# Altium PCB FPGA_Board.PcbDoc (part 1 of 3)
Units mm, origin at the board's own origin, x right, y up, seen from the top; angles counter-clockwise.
Board outline 130 x 90 mm, 4 copper layers (Component Side, Signal Layer 1, Signal Layer 2, Bottom Layer), stack 0.651 mm thick; 303 components, 175 nets, 968 pads, 775 vias.
Unrouted connection lines stored in the file: 193.
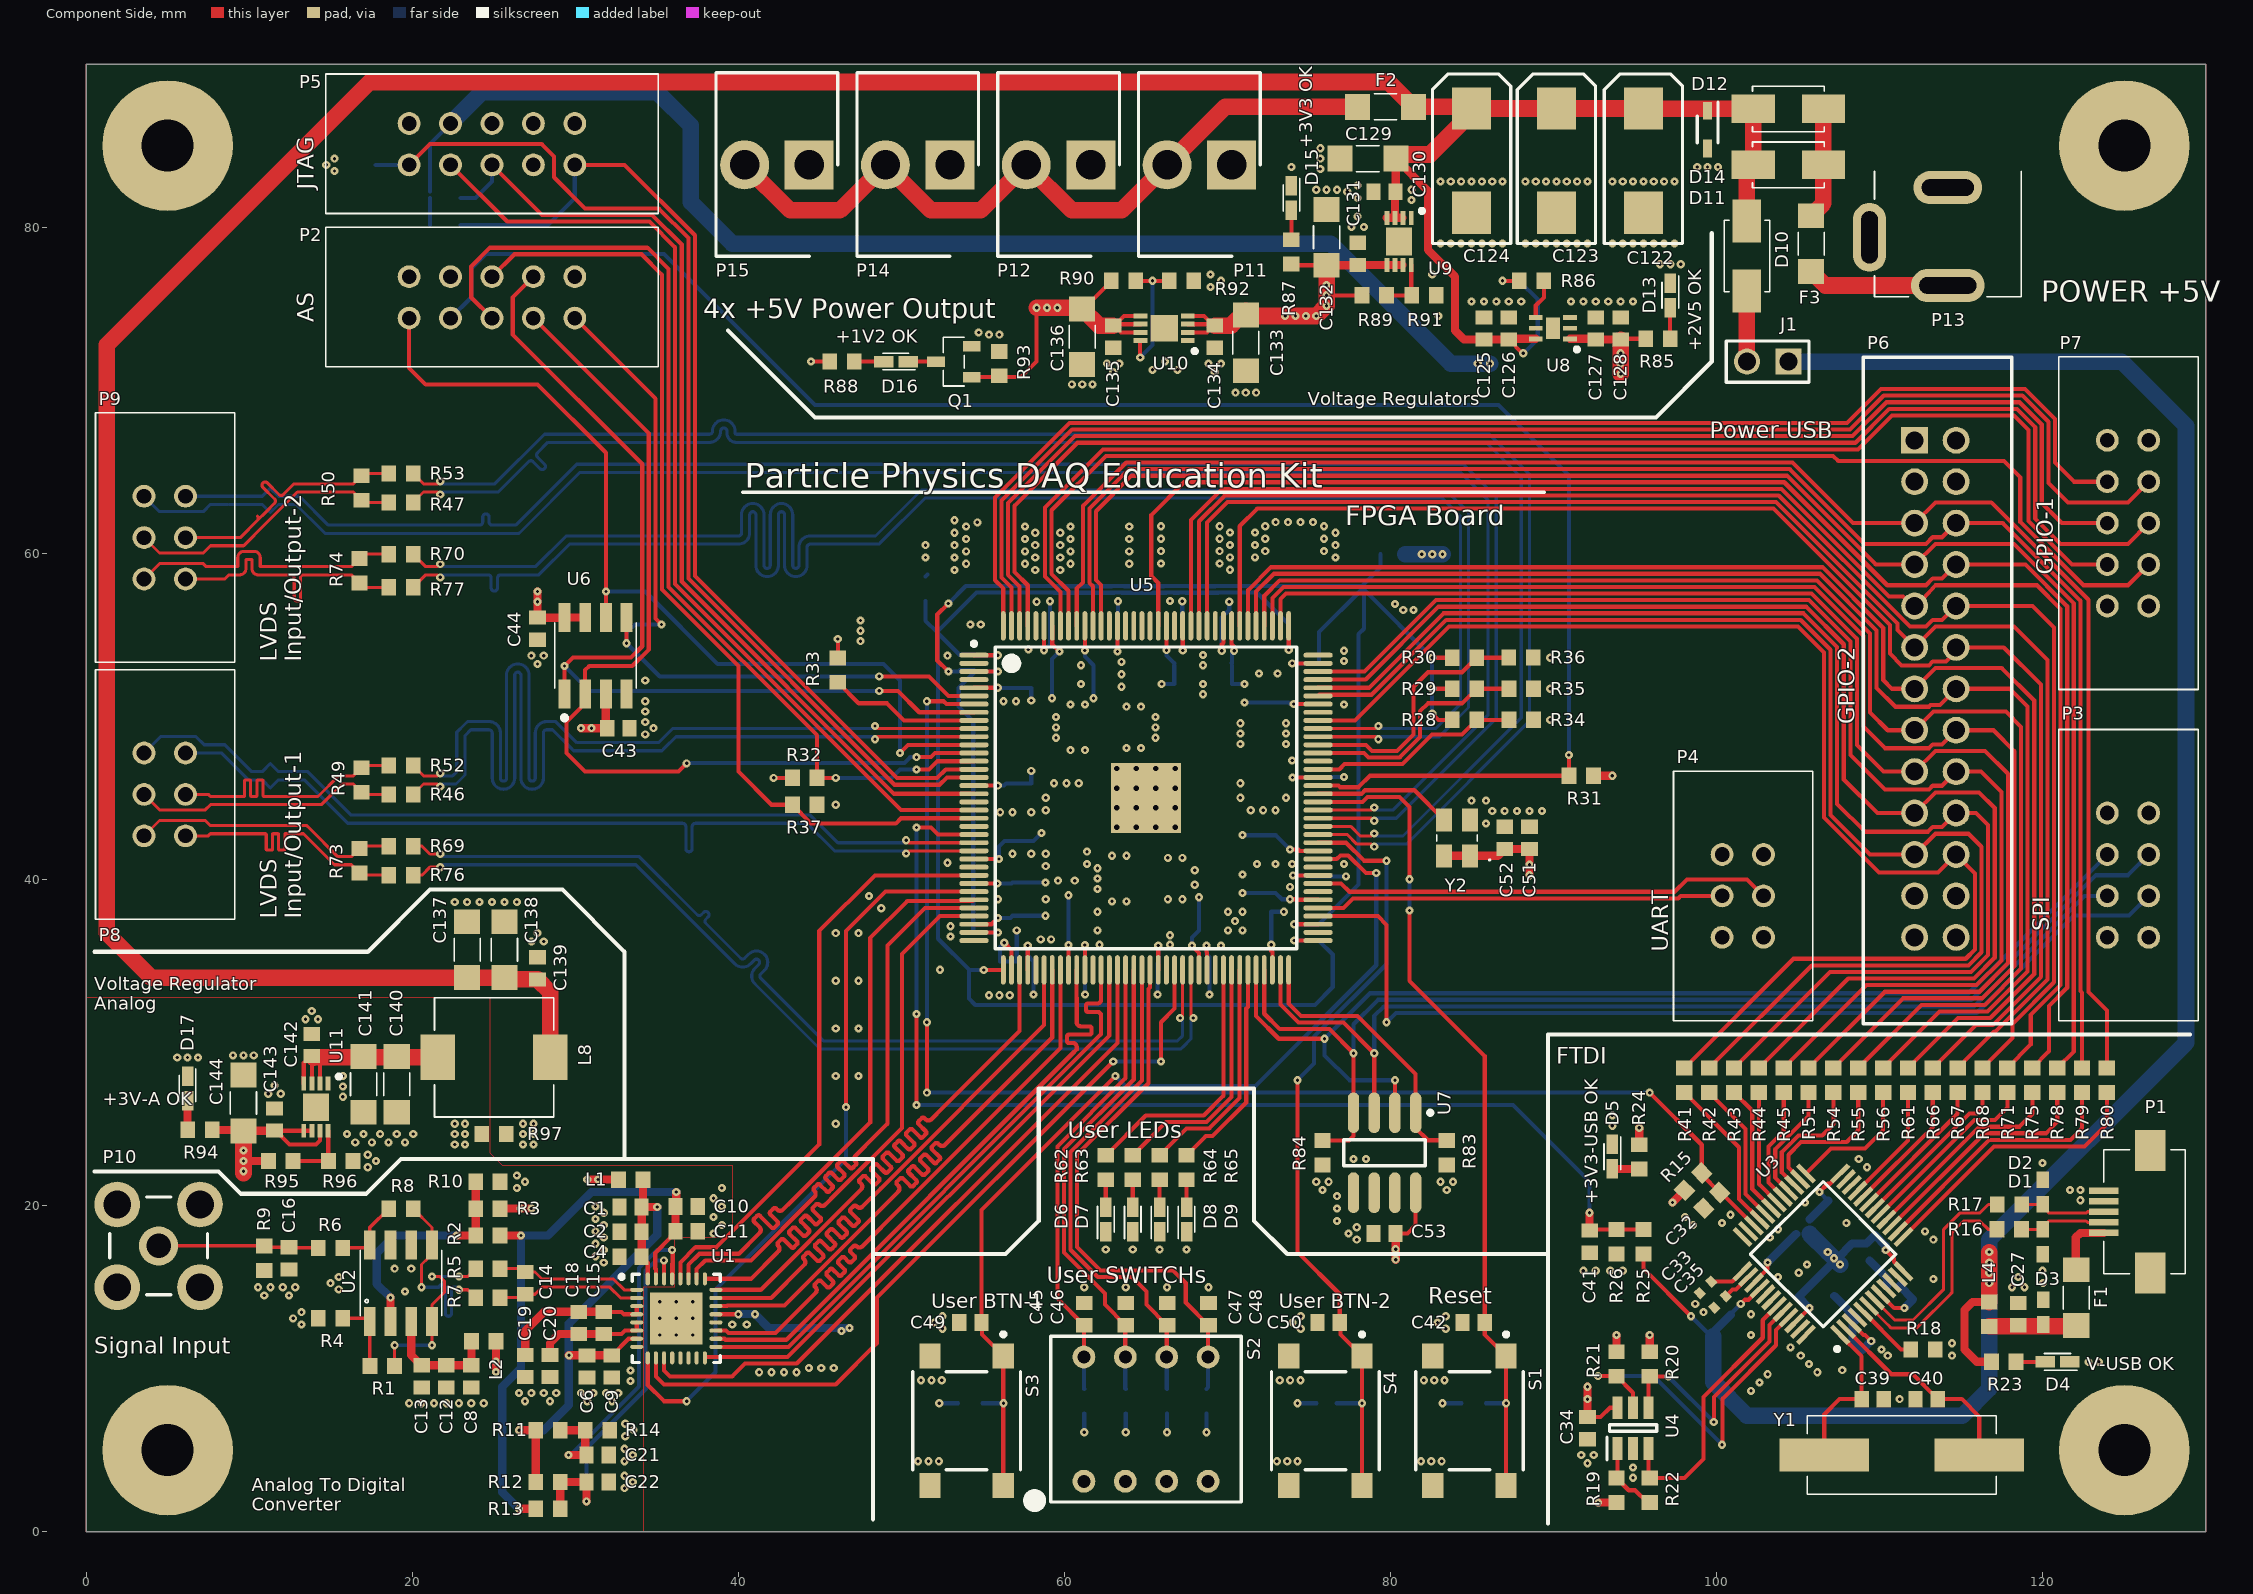
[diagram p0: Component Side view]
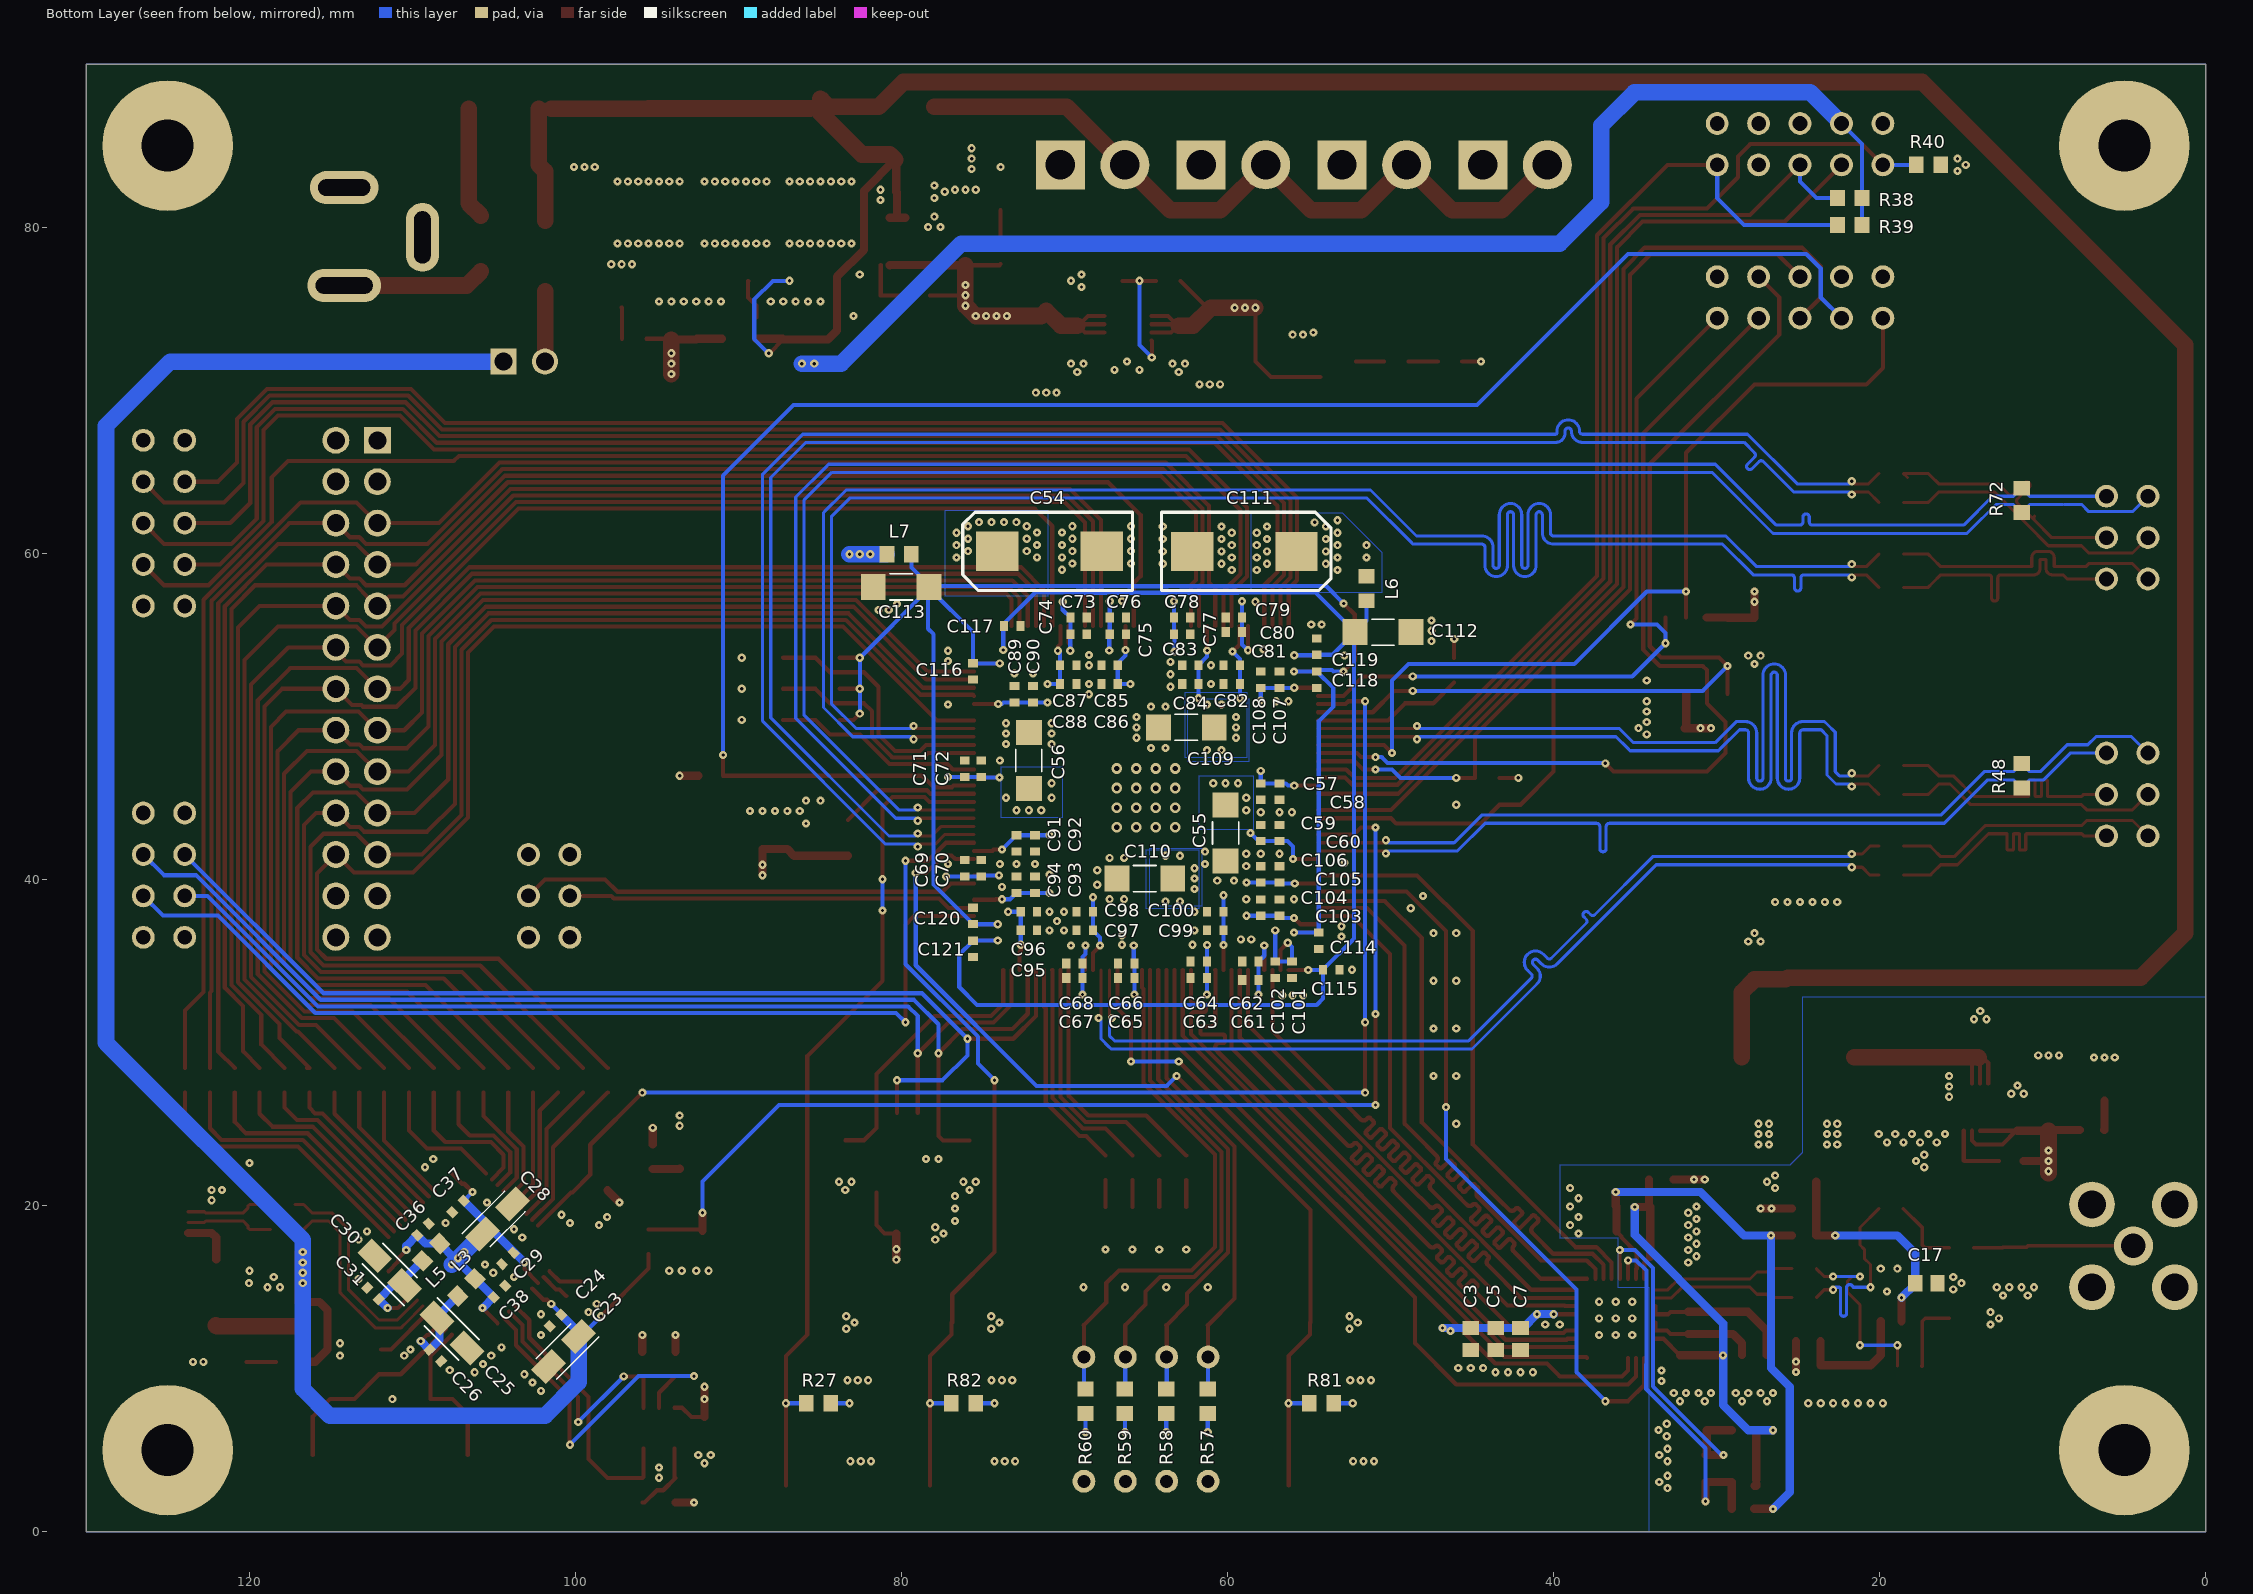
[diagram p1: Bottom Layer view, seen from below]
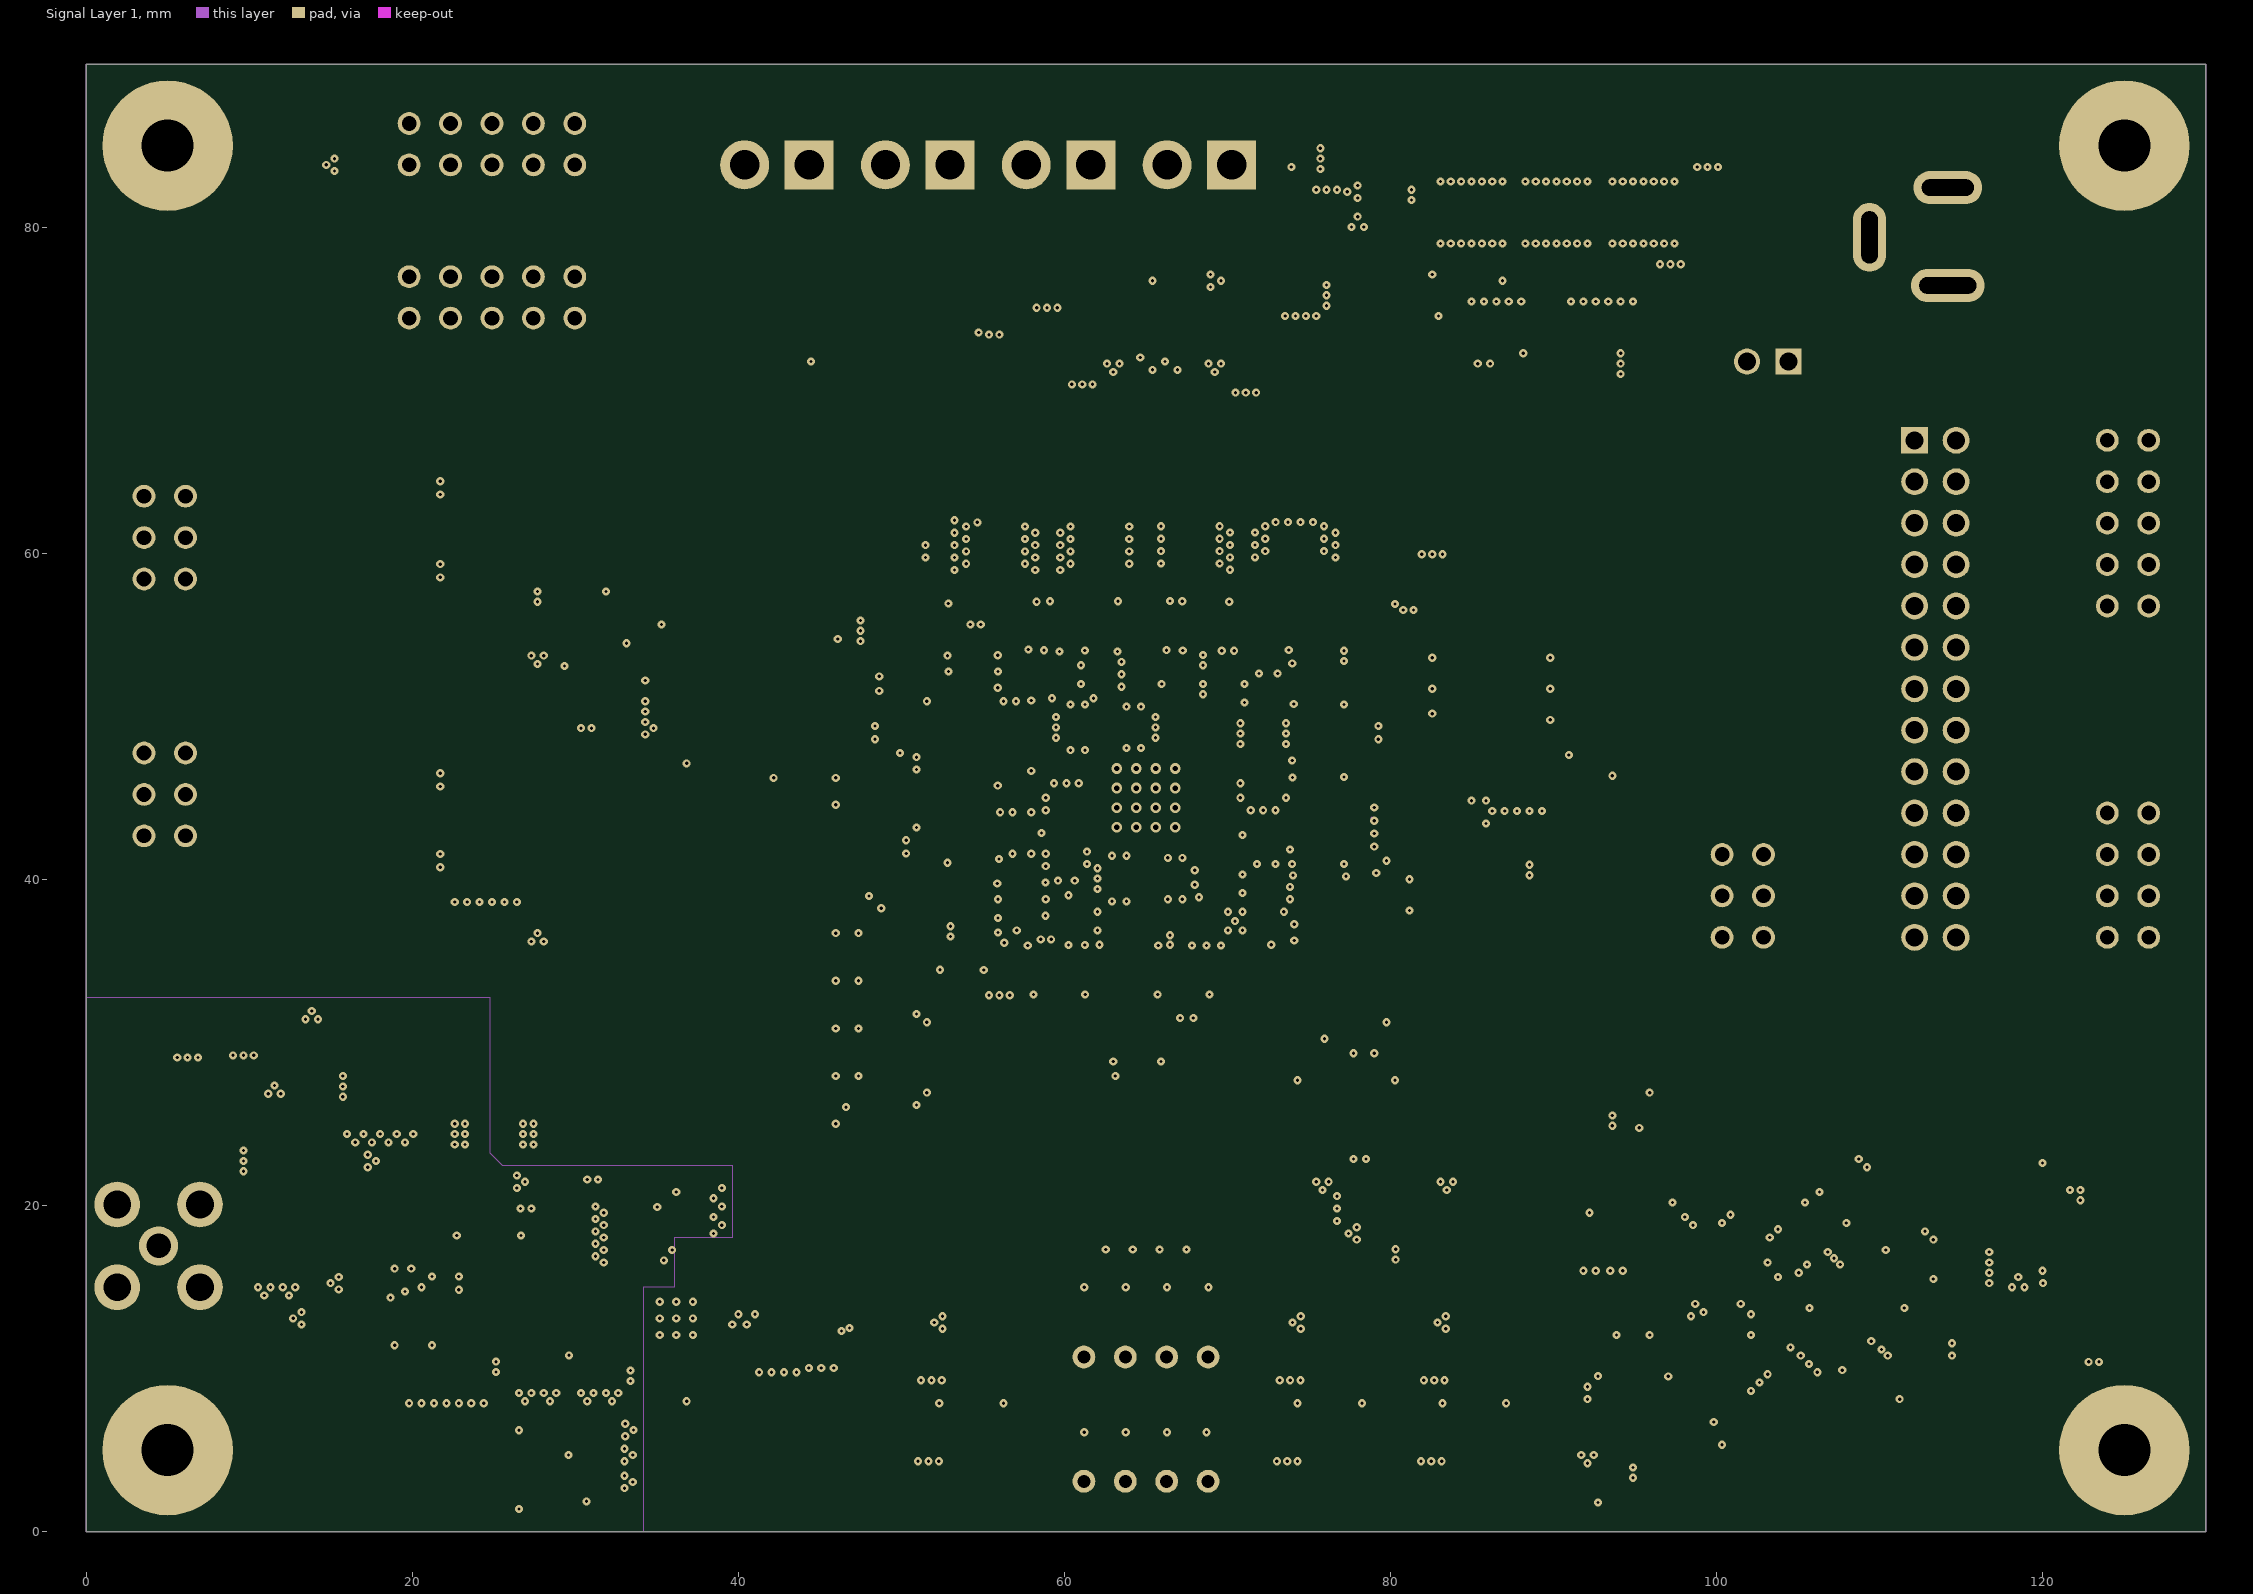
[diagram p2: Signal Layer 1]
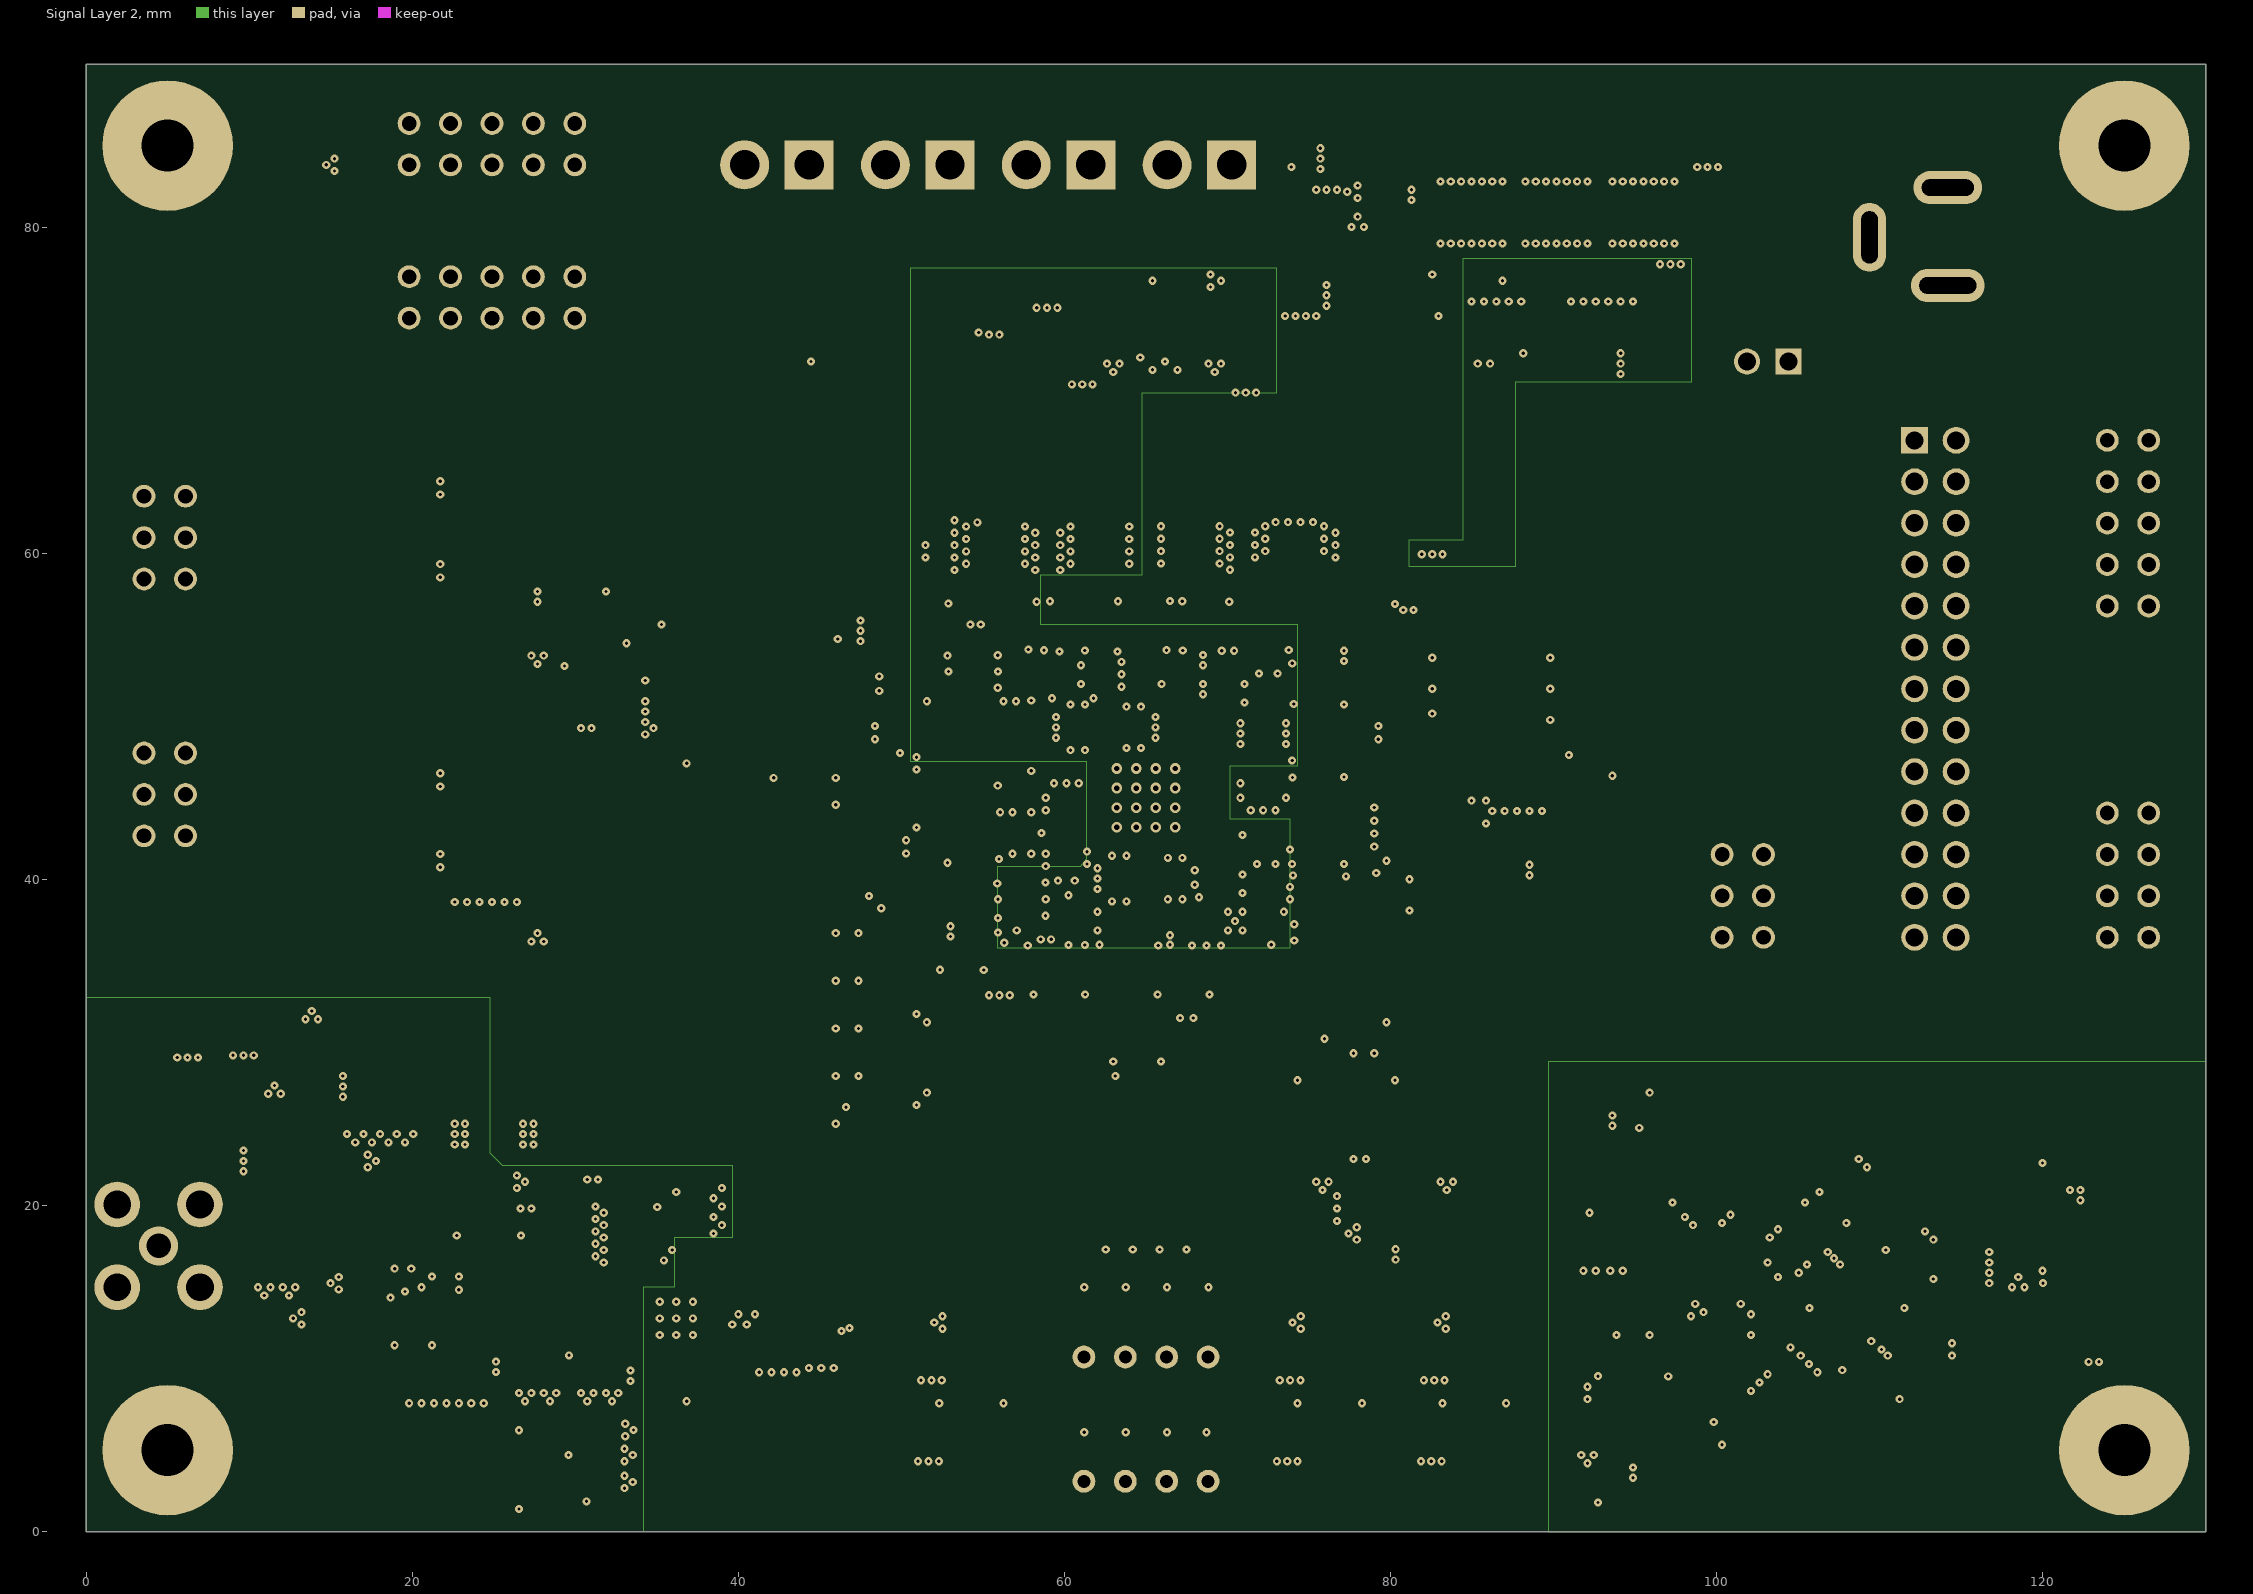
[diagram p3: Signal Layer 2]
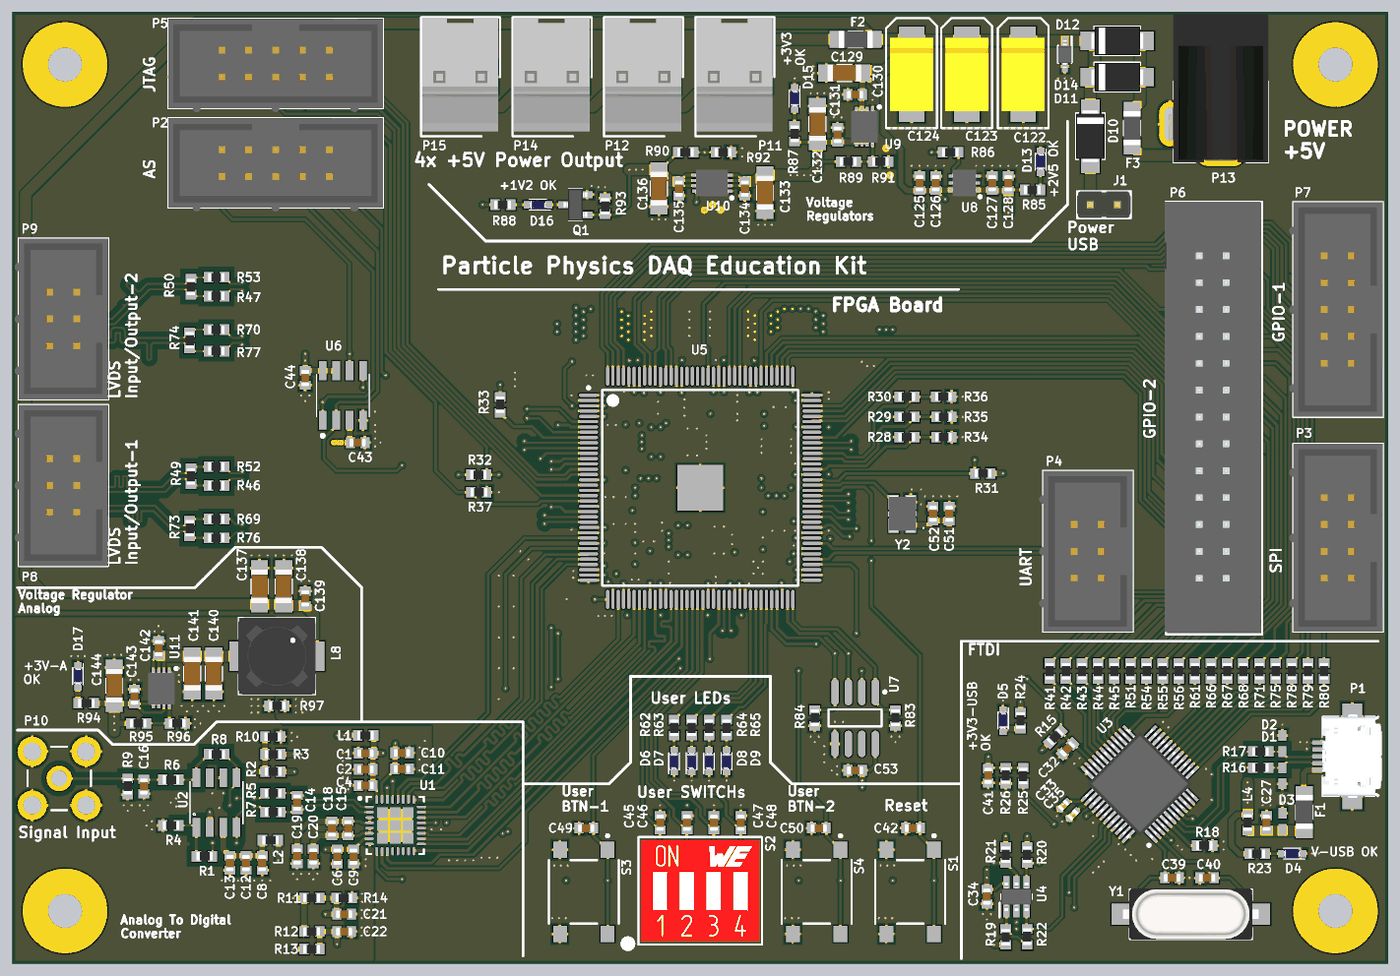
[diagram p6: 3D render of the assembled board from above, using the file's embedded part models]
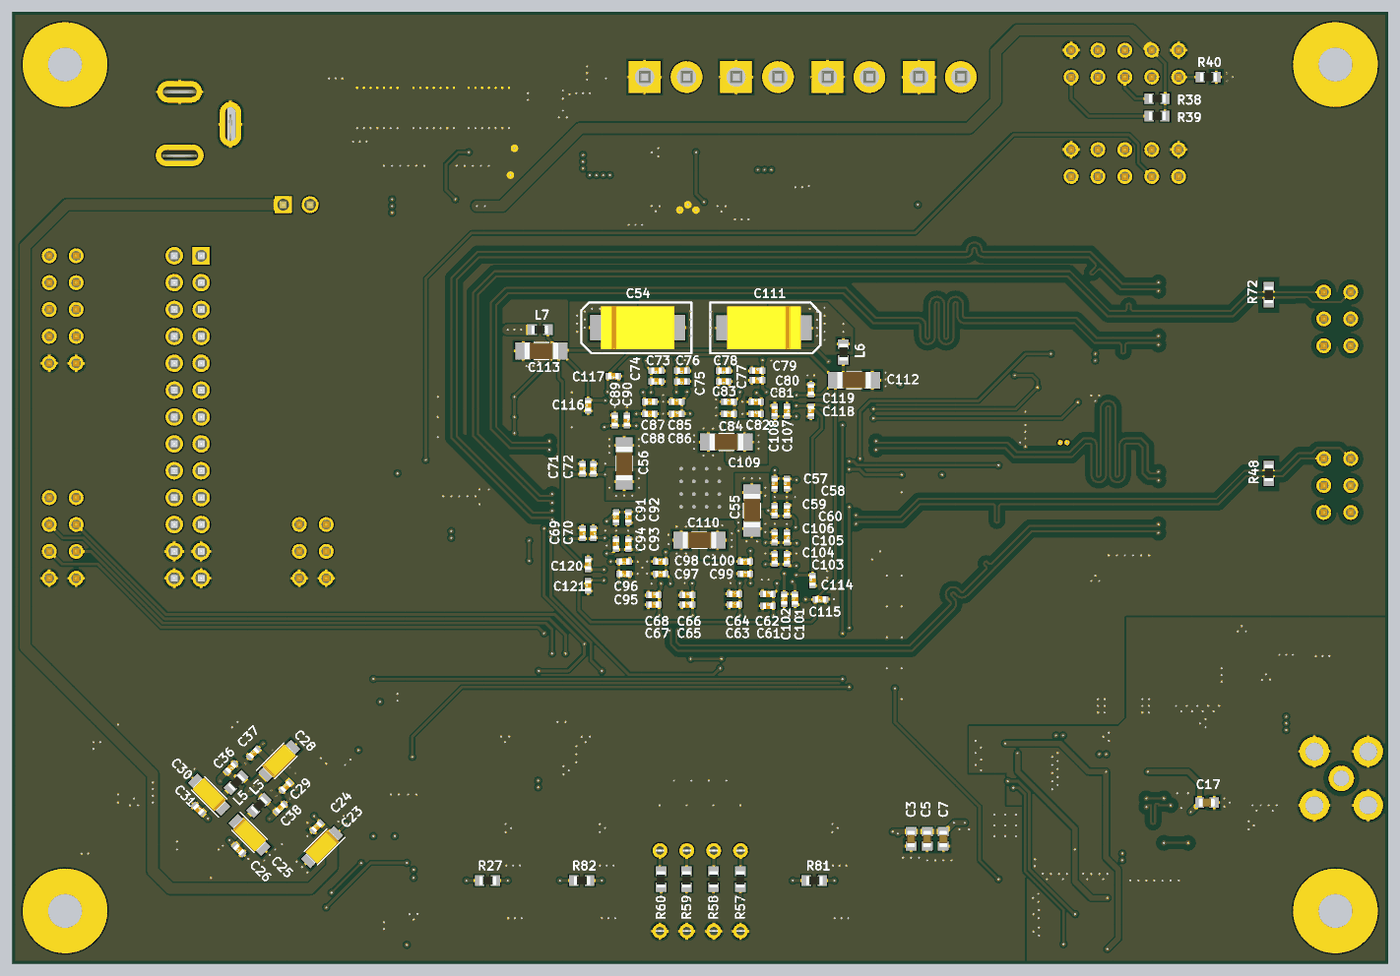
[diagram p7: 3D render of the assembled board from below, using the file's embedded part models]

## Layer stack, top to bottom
Top Solder: solder mask 0.0102, Solder Resist, Dk 3.5
Component Side: signal copper 0.0356
Dielectric 1: prepreg 0.127, FR-4, Dk 4.2
Signal Layer 1: signal copper 0.036
Dielectric 3: core 0.254, Dk 4.2
Signal Layer 2: signal copper 0.036
Dielectric 2: prepreg 0.127, Dk 4.2
Bottom Layer: signal copper 0.0356
Solder Side: solder mask 0.0102, Solder Resist, Dk 3.5

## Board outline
0,0 130,0 130,90 0,90

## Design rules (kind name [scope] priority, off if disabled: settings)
AcuteAngle [All] p1: minimum=6.00000000000000E+0001 checktracksonly=FALSE
BoardOutlineClearance [All] p1: gap=0.3 ignorepadtopadclearanceinfootprint=FALSE
Clearance Clearance_50R [InNetClass('50R')] p1: gap=0.15 ignorepadtopadclearanceinfootprint=FALSE except(0: Arc-Hole Track-Hole SMDPad-Hole THPad-Hole Via-Hole Fill-Hole Poly-Hole Region-Hole Text-Hole; 0.5: Arc-Fill Arc-Poly Arc-Region Track-Fill Track-Poly Track-Region SMDPad-Fill SMDPad-Poly SMDPad-Region THPad-Fill THPad-Poly THPad-Region Via-Fill Via-Poly Via-Region Fill-Fill Fill-Poly Fill-Region Poly-Poly Poly-Region Region-Region)
Clearance Clearance_DiffPair [(InDifferentialPairClass('All Differential Pairs'))] p2: gap=0.15 ignorepadtopadclearanceinfootprint=FALSE except(0: Arc-Hole Track-Hole SMDPad-Hole THPad-Hole Via-Hole Fill-Hole Poly-Hole Region-Hole Text-Hole; 0.5: Arc-Poly Track-Poly SMDPad-Poly THPad-Poly Via-Poly Fill-Poly Poly-Poly)
Clearance [All] p3: gap=0.15 ignorepadtopadclearanceinfootprint=FALSE except(0: Arc-Hole Track-Hole SMDPad-Hole THPad-Hole Via-Hole Fill-Hole Poly-Hole Region-Hole Text-Hole)
DiffPairsRouting [All] p1: maxlimit=0.31 minlimit=0.31 mostfreqgap=0.31 toplayer_minwidth=0.19 toplayer_maxwidth=0.19 toplayer_prefwidth=0.19 midlayer1_minwidth=0.19 midlayer1_maxwidth=0.19 midlayer1_prefwidth=0.19 midlayer2_minwidth=0.19 midlayer2_maxwidth=0.19 midlayer2_prefwidth=0.19 bottomlayer_minwidth=0.19 bottomlayer_maxwidth=0.19 bottomlayer_prefwidth=0.19 maxuncoupledlength=12.7
HoleSize [All] p1: absolutevalues=TRUE maxlimit=4 minlimit=0.025 maxpercent=80.000 minpercent=20.000
MatchedLengths MatchedLengths_1 [InNetClass('ADC_DATA')] p1: tolerance=1 checknetsindiffpair=FALSE checkdiffpairvsdiffpair=TRUE checkxsignals=TRUE checkothers=TRUE
MatchedLengths [All] p2: tolerance=1 checknetsindiffpair=TRUE checkdiffpairvsdiffpair=FALSE checkxsignals=FALSE checkothers=FALSE
MinimumSolderMaskSliver [All] p1: minsoldermaskwidth=0.065
PolygonConnect [All] p1: thpad.connectstyle=Relief thpad.reliefconductorwidth=0.254 thpad.reliefentries=4 thpad.polygonreliefangle="90 Angle" thpad.airgapwidth=0.254 smdpad.connectstyle=Relief smdpad.reliefconductorwidth=0.254 smdpad.reliefentries=4 smdpad.polygonreliefangle="90 Angle" smdpad.airgapwidth=0.254 via.connectstyle=Direct via.reliefconductorwidth=0.254 via.reliefentries=4 via.polygonreliefangle="90 Angle" via.airgapwidth=0.254
RoutingVias [All] p1: holewidth=0.2 width=0.5 viastyle="Through Hole" minholewidth=0.2 minwidth=0.5 maxholewidth=0.2 maxwidth=0.5
SilkToSilkClearance [All] p1: silktosilkclearance=0.1
SilkToSolderMaskClearance [IsPad] p1: minsilkscreentomaskgap=0.1 clearancetoexposedcopper=TRUE
SolderMaskExpansion [All] p1: expansion=0.102
Width Width_50R [InNetClass('50R')] p1: maxlimit=0.22 minlimit=0.22 preferedwidth=0.22
Width [All] p2: maxlimit=1.016 minlimit=0.254 preferedwidth=0.508
25 further rules are at their usual default settings.

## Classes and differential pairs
component class Main: P10
component class U_ADC: C1 C2 C3 C4 C5 C6 C7 C8 C9 C10 C11 C12 C13 C14 C15 C16 C17 C18 C19 C20 C21 C22 L1 L2 R1 R2 R3 R4 R5 R6 R7 R8 R9 R10 R11 R12 R13 R14 U1 U2
component class U_Communication: C23 C24 C25 C26 C27 C28 C29 C30 C31 C32 C33 C34 C35 C36 C37 C38 C39 C40 C41 D1 D2 D3 D4 D5 F1 L3 L4 L5 P1 R15 R16 R17 R18 R19 R20 R21 R22 R23 R24 R25 R26 U3 U4 Y1
component class U_FPGA_Power: C54 C55 C56 C57 C58 C59 C60 C61 C62 C63 C64 C65 C66 C67 C68 C69 C70 C71 C72 C73 C74 C75 C76 C77 C78 C79 C80 C81 C82 C83 C84 C85 C86 C87 C88 C89 C90 C91 C92 C93 C94 C95 C96 C97 C98 C99 C100 C101 C102 C103 C104 C105 C106 C107 C108 C109 C110 C111 C112 C113 C114 C115 C116 C117 C118 C119 C120 C121 L6 L7
component class U_FPGA: C42 C43 C44 C45 C46 C47 C48 C49 C50 C51 C52 C53 D6 D7 D8 D9 P2 P3 P4 P5 P6 P7 P8 P9 R27 R28 R29 R30 R31 R32 R33 R34 R35 R36 R37 R38 R39 R40 R41 R42 R43 R44 R45 R46 R47 R48 R49 R50 R51 R52 R53 R54 R55 R56 R57 R58 R59 R60 R61 R62 R63 R64 R65 R66 R67 R68 R69 R70 R71 R72 R73 R74 R75 R76 R77 R78 R79 R80 R81 R82 R83 R84 S1 S2 S3 S4 U5 U6 U7 Y2
component class U_Power: C122 C123 C124 C125 C126 C127 C128 C129 C130 C131 C132 C133 C134 C135 C136 C137 C138 C139 C140 C141 C142 C143 C144 D10 D11 D12 D13 D14 D15 D16 D17 F2 F3 J1 L8 P11 P12 P13 P14 P15 Q1 R85 R86 R87 R88 R89 R90 R91 R92 R93 R94 R95 R96 R97 U8 U9 U10 U11
net class 50R: NetC16_2 NetR1_1 NetR6_2
net class ADC_DATA: NetU1_16 NetU1_17 NetU1_18 NetU1_19 NetU1_22 NetU1_23 NetU1_24 NetU1_25 NetU1_26 NetU1_27
differential pair EXT_In: +EXT_In_P -EXT_In_N
differential pair EXT_Out0_R: +EXT_Out0_R_P -EXT_Out0_R_N
differential pair EXT_Out0: +EXT_Out0_P -EXT_Out0_N
differential pair EXT_Out1_R: +EXT_Out1_R_P -EXT_Out1_R_N
differential pair EXT_Out1: +EXT_Out1_P -EXT_Out1_N
differential pair Full_R: +Full_R_P -Full_R_N
differential pair Full: +Full_P -Full_N
differential pair InR: +InR_P -InR_N
differential pair In: +In_P -In_N
differential pair Ready_R: +Ready_R_P -Ready_R_N
differential pair Ready: +Ready_P -Ready_N
differential pair TRG: +TRG_P -TRG_N
differential pair D: +D_P -D_N
differential pair USB: +USB_P -USB_N

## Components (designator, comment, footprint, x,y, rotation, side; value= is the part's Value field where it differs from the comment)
C1 "1u" SMD_CAPACITOR_0603 33.389,19.911 r180 top
C2 "100nF" SMD_CAPACITOR_0603 33.389,18.387 r180 top
C3 "1uF" SMD_CAPACITOR_0603 45.085,11.811 r270 bottom
C4 "10nF" SMD_CAPACITOR_0603 33.389,16.863 r180 top
C5 "100nF" SMD_CAPACITOR_0603 43.561,11.811 r270 bottom
C6 "100nF" SMD_CAPACITOR_0603 30.722,10.132 r270 top
C7 "10nF" SMD_CAPACITOR_0603 42.037,11.811 r270 bottom
C8 "1u" SMD_CAPACITOR_0603 23.622,9.525 r270 top
C9 "10nF" SMD_CAPACITOR_0603 32.246,10.132 r270 top
C10 "2u2" SMD_CAPACITOR_0603 36.83,19.939 r180 top
C11 "100n" SMD_CAPACITOR_0603 36.83,18.415 r180 top
C12 "100nF" SMD_CAPACITOR_0603 22.098,9.525 r270 top
C13 "10nF" SMD_CAPACITOR_0603 20.574,9.525 r270 top
C14 "12p" SMD_CAPACITOR_0603 26.924,15.24 r90 top
C15 "100n" SMD_CAPACITOR_0603 31.738,12.799 r90 top
C16 "D.N.P." SMD_CAPACITOR_0603 12.446,16.764 r90 top
C17 "100nF" SMD_CAPACITOR_0603 17.145,15.24 r0 bottom
C18 "2u2" SMD_CAPACITOR_0603 30.214,12.799 r90 top
C19 "1u" SMD_CAPACITOR_0603 26.924,10.16 r90 top
C20 "1u" SMD_CAPACITOR_0603 28.448,10.16 r90 top
C21 "100nF" SMD_CAPACITOR_0603 31.369,4.699 r0 top
C22 "100nF" SMD_CAPACITOR_0603 31.369,3.048 r0 top
C23 "4u7" SMD_CAPACITOR_POL_A_3216 100.711,11.049 r315 bottom
C24 "100n" SMD_CAPACITOR_0402 101.219,12.954 r135 bottom
C25 "4u7" SMD_CAPACITOR_POL_A_3216 107.569,12.192 r225 bottom
C26 "100n" SMD_CAPACITOR_0402 108.585,10.795 r45 bottom
C27 "10n" SMD_CAPACITOR_0603 118.491,13.335 r270 top
C28 "4u7" SMD_CAPACITOR_POL_A_3216 104.775,19.177 r135 bottom
C29 "100n" SMD_CAPACITOR_0402 104.14,16.764 r135 bottom
C30 "4u7" SMD_CAPACITOR_POL_A_3216 111.379,16.002 r45 bottom
C31 "100n" SMD_CAPACITOR_0402 112.395,14.605 r225 bottom
C32 "10n" SMD_CAPACITOR_0603 99.695,20.32 r45 top
C33 "100n" SMD_CAPACITOR_0402 99.314,14.986 r45 top
C34 "100n" SMD_CAPACITOR_0603 92.075,6.35 r90 top
C35 "100n" SMD_CAPACITOR_0402 100.203,14.097 r45 top
C36 "100n" SMD_CAPACITOR_0402 109.347,18.542 r315 bottom
C37 "100n" SMD_CAPACITOR_0402 107.188,19.939 r135 bottom
C38 "100n" SMD_CAPACITOR_0402 104.648,14.732 r315 bottom
C39 "22p" SMD_CAPACITOR_0603 109.568,8.128 r180 top
C40 "22p" SMD_CAPACITOR_0603 112.87,8.128 r0 top
C41 "100n" SMD_CAPACITOR_0603 92.202,17.78 r90 top
C42 "10n" SMD_CAPACITOR_0603 85.09,12.827 r180 top
C43 "100n" SMD_CAPACITOR_0603 32.639,49.276 r180 top
C44 "100n" SMD_CAPACITOR_0603 27.686,55.372 r90 top
C45 "10n" SMD_CAPACITOR_0603 61.214,13.335 r270 top
C46 "10n" SMD_CAPACITOR_0603 63.754,13.335 r270 top
C47 "10n" SMD_CAPACITOR_0603 66.294,13.335 r270 top
C48 "10n" SMD_CAPACITOR_0603 68.834,13.335 r270 top
C49 "10n" SMD_CAPACITOR_0603 54.229,12.827 r180 top
C50 "10n" SMD_CAPACITOR_0603 76.2,12.827 r180 top
C51 "1u" SMD_CAPACITOR_0603 88.519,42.545 r90 top
C52 "100nF" SMD_CAPACITOR_0603 86.995,42.545 r90 top
C53 "100n" SMD_CAPACITOR_0603 79.629,18.288 r0 top
C54 "100u" CAP_Tantalum_D 70.913,60.118 r180 bottom
C55 "10u" SMD_CAPACITOR_1206 60.118,42.846 r90 bottom
C56 "10u" SMD_CAPACITOR_1206 72.183,47.291 r270 bottom
C57 "100n" SMD_CAPACITOR_0402 57.959,45.386 r90 bottom
C58 "10n" SMD_CAPACITOR_0402 56.816,45.386 r90 bottom
C59 "100n" SMD_CAPACITOR_0402 57.959,42.846 r270 bottom
C60 "10n" SMD_CAPACITOR_0402 56.816,42.846 r270 bottom
C61 "100n" SMD_CAPACITOR_0402 58.594,33.829 r180 bottom
C62 "10n" SMD_CAPACITOR_0402 58.594,34.972 r180 bottom
C63 "100n" SMD_CAPACITOR_0402 61.769,33.956 r180 bottom
C64 "10n" SMD_CAPACITOR_0402 61.769,34.972 r180 bottom
C65 "100n" SMD_CAPACITOR_0402 66.214,33.956 r180 bottom
C66 "10n" SMD_CAPACITOR_0402 66.214,34.845 r180 bottom
C67 "100n" SMD_CAPACITOR_0402 69.389,33.956 r180 bottom
C68 "10n" SMD_CAPACITOR_0402 69.389,34.845 r180 bottom
C69 "100n" SMD_CAPACITOR_0402 76.12,40.687 r270 bottom
C70 "10n" SMD_CAPACITOR_0402 75.104,40.687 r270 bottom
C71 "100n" SMD_CAPACITOR_0402 76.12,46.783 r270 bottom
C72 "10n" SMD_CAPACITOR_0402 75.104,46.783 r270 bottom
C73 "100n" SMD_CAPACITOR_0402 69.135,56.054 r0 bottom
C74 "10n" SMD_CAPACITOR_0402 69.135,55.038 r0 bottom
C75 "100n" SMD_CAPACITOR_0402 66.722,55.038 r0 bottom
C76 "10n" SMD_CAPACITOR_0402 66.722,56.054 r0 bottom
C77 "100n" SMD_CAPACITOR_0402 62.785,55.038 r0 bottom
C78 "10n" SMD_CAPACITOR_0402 62.785,56.054 r0 bottom
C79 "100n" SMD_CAPACITOR_0402 59.61,56.054 r180 bottom
C80 "10n" SMD_CAPACITOR_0402 59.61,55.165 r180 bottom
C81 "10n" SMD_CAPACITOR_0402 59.737,53.133 r180 bottom
C82 "100n" SMD_CAPACITOR_0402 59.737,51.99 r180 bottom
C83 "10n" SMD_CAPACITOR_0402 62.277,53.133 r180 bottom
C84 "100n" SMD_CAPACITOR_0402 62.277,51.99 r180 bottom
C85 "10n" SMD_CAPACITOR_0402 67.23,53.133 r180 bottom
C86 "100n" SMD_CAPACITOR_0402 67.23,51.99 r180 bottom
C87 "10n" SMD_CAPACITOR_0402 69.77,53.133 r0 bottom
C88 "100n" SMD_CAPACITOR_0402 69.77,51.99 r0 bottom
C89 "10n" SMD_CAPACITOR_0402 73.072,51.355 r270 bottom
C90 "100n" SMD_CAPACITOR_0402 71.929,51.355 r270 bottom
C91 "10n" SMD_CAPACITOR_0402 72.945,42.211 r90 bottom
C92 "100n" SMD_CAPACITOR_0402 71.802,42.211 r90 bottom
C93 "10n" SMD_CAPACITOR_0402 71.802,39.671 r270 bottom
C94 "100n" SMD_CAPACITOR_0402 72.945,39.671 r270 bottom
C95 "10n" SMD_CAPACITOR_0402 72.183,36.877 r0 bottom
C96 "100n" SMD_CAPACITOR_0402 72.183,38.02 r0 bottom
C97 "10n" SMD_CAPACITOR_0402 68.754,36.877 r180 bottom
C98 "100n" SMD_CAPACITOR_0402 68.754,38.02 r180 bottom
C99 "10n" SMD_CAPACITOR_0402 60.753,36.877 r180 bottom
C100 "100n" SMD_CAPACITOR_0402 60.753,38.02 r180 bottom
C101 "10n" SMD_CAPACITOR_0402 56.054,34.464 r90 bottom
C102 "100n" SMD_CAPACITOR_0402 57.07,34.464 r90 bottom
C103 "10n" SMD_CAPACITOR_0402 56.816,38.274 r270 bottom
C104 "100n" SMD_CAPACITOR_0402 57.959,38.274 r270 bottom
C105 "10n" SMD_CAPACITOR_0402 56.816,40.306 r270 bottom
C106 "100n" SMD_CAPACITOR_0402 57.959,40.306 r270 bottom
C107 "10n" SMD_CAPACITOR_0402 56.816,52.244 r270 bottom
C108 "100n" SMD_CAPACITOR_0402 57.959,52.244 r270 bottom
C109 "10u" SMD_CAPACITOR_1206 62.531,49.323 r180 bottom
C110 "10u" SMD_CAPACITOR_1206 65.071,40.052 r180 bottom
C111 "100u" CAP_Tantalum_D 58.975,60.118 r0 bottom
C112 "10u" SMD_CAPACITOR_1206 50.466,55.165 r0 bottom
C113 "10u" SMD_CAPACITOR_1206 80.01,57.935 r180 bottom
C114 "100n" SMD_CAPACITOR_0402 54.403,36.242 r90 bottom
C115 "100n" SMD_CAPACITOR_0402 53.641,34.464 r0 bottom
C116 "100n" SMD_CAPACITOR_0402 75.612,52.752 r90 bottom
C117 "100n" SMD_CAPACITOR_0402 73.199,55.546 r0 bottom
C118 "100n" SMD_CAPACITOR_0402 54.53,52.244 r90 bottom
C119 "100n" SMD_CAPACITOR_0402 54.53,54.276 r270 bottom
C120 "100n" SMD_CAPACITOR_0402 75.612,37.766 r270 bottom
C121 "100n" SMD_CAPACITOR_0402 75.612,35.734 r90 bottom
C122 "100u" CAP_Tantalum_D 95.504,84.074 r270 top
C123 "100u" CAP_Tantalum_D 90.17,84.074 r270 top
C124 "100u" CAP_Tantalum_D 84.963,84.074 r270 top
C125 "1u" SMD_CAPACITOR_0603 85.725,73.787 r270 top
C126 "100n" SMD_CAPACITOR_0603 87.249,73.787 r270 top
C127 "1u" SMD_CAPACITOR_0603 92.583,73.787 r270 top
C128 "100n" SMD_CAPACITOR_0603 94.107,73.787 r270 top
C129 "10u" SMD_CAPACITOR_1206 78.613,84.201 r0 top
C130 "100n" SMD_CAPACITOR_0603 79.629,82.169 r0 top
C131 "100n" SMD_CAPACITOR_0603 77.978,78.359 r270 top
C132 "10u" SMD_CAPACITOR_1206 76.073,79.375 r270 top
C133 "10u" SMD_CAPACITOR_1206 71.12,72.898 r90 top
C134 "100n" SMD_CAPACITOR_0603 69.215,73.279 r90 top
C135 "100n" SMD_CAPACITOR_0603 62.992,73.279 r90 top
C136 "10u" SMD_CAPACITOR_1206 61.087,73.279 r90 top
C137 "10u" SMD_CAPACITOR_1206 23.368,35.687 r270 top
C138 "10u" SMD_CAPACITOR_1206 25.654,35.687 r270 top
C139 "1u" SMD_CAPACITOR_0603 27.686,34.544 r270 top
C140 "10u" SMD_CAPACITOR_1206 19.05,27.432 r90 top
C141 "10u" SMD_CAPACITOR_1206 17.018,27.432 r90 top
C142 "100n" SMD_CAPACITOR_0603 13.843,29.845 r270 top
C143 "100n" SMD_CAPACITOR_0603 11.557,25.273 r270 top
C144 "10u" SMD_CAPACITOR_1206 9.652,26.289 r270 top
D1 "5V" sm_esd_0603 119.982,17.78 r90 top
D2 "5V" sm_esd_0603 119.982,20.828 r270 top
D3 "5V" sm_esd_0603 120.015,13.462 r270 top
D4 "GREEN" SMD_LED_0603 120.904,10.414 r180 top
D5 "GREEN" SMD_LED_0603 93.599,22.999 r270 top
D6 "RED" SMD_LED_0603 62.535,19.152 r90 top
D7 "RED" SMD_LED_0603 64.186,19.152 r90 top
D8 "RED" SMD_LED_0603 65.837,19.152 r90 top
D9 "RED" SMD_LED_0603 67.488,19.152 r90 top
D10 "B340A" SMD_DO-214AC 101.854,78.232 r90 top
D11 "B340A" SMD_DO-214AC 104.394,83.82 r180 top
D12 "SD05.TCT" SMD_SOD-323 99.441,85.979 r270 top
D13 "GREEN" SMD_LED_0603 97.155,75.819 r270 top
D14 "B340A" SMD_DO-214AC 104.394,87.249 r180 top
D15 "GREEN" SMD_LED_0603 73.914,81.788 r270 top
D16 "GREEN" SMD_LED_0603 49.657,71.755 r180 top
D17 "GREEN" SMD_LED_0603 6.223,27.178 r270 top
F1 "1A/SLOW" SMD_RESISTOR_1206 122.047,14.351 r270 top
F2 "3A/SLOW" SMD_RESISTOR_1206 79.688,87.376 r180 top
F3 "3A/SLOW" SMD_RESISTOR_1206 105.791,78.994 r90 top
J1 "Header_2pin_1row" 61300211121 104.394,71.755 r180 top
L1 "1k@100MHz" SMD_RES_0603 33.401,21.59 r180 top
L2 "1k@100MHz" SMD_RES_0603 24.384,11.684 r0 top
L3 "600R/0.5A" SMD_RES_0603 106.68,14.986 r135 bottom
L4 "33R-100 MHz, 3A" SMD_RES_0603 116.713,13.335 r90 top
L5 "600R/0.5A" SMD_RES_0603 108.839,17.145 r135 bottom
L6 "1k@100MHz" SMD_RES_0603 51.482,57.832 r270 bottom
L7 "1k@100MHz" SMD_RES_0603 80.137,59.944 r0 bottom
L8 "220uH" SMD_INDUCTOR_7.3MM 25.019,29.083 r180 top
P1 "Micro USB B" SMD_USB_MICRO_B 123.736,19.618 r90 top
P2 "Header 2x5" THT_HEADER_100MIL_2X5_MALE_SHROUDED 24.892,75.692 r90 top
P3 "Header 2x4" THT_HEADER_100MIL_2X4_MALE_SHROUDED 125.222,38.989 r0 top
P4 "Header 2x3" THT_HEADER_100MIL_2X3_MALE_SHROUDED 101.6,38.989 r0 top
P5 "Header 2x5" THT_HEADER_100MIL_2X5_MALE_SHROUDED 24.892,85.09 r90 top
P6 "Header 2x13" THT_HEADER_2x13 112.141,66.929 r270 top
P7 "Header 2x5" THT_HEADER_100MIL_2X5_MALE_SHROUDED 125.222,61.849 r0 top
P8 "Header 2x3" THT_HEADER_100MIL_2X3_MALE_SHROUDED 4.826,45.212 r0 top
P9 "Header 2x3" THT_HEADER_100MIL_2X3_MALE_SHROUDED 4.826,60.96 r0 top
P10 "SMA_Female" SMA5.08-H 4.445,17.526 r0 top
P11 "09-65-2028" SHDR2W165P0X396_1X2_716X1062X1425P 70.254,83.82 r180 top
P12 "09-65-2028" SHDR2W165P0X396_1X2_716X1062X1425P 61.618,83.82 r180 top
P13 "2.1mm" THT_POWER_JACK_2.1/2.5 114.173,82.423 r90 top
P14 "09-65-2028" SHDR2W165P0X396_1X2_716X1062X1425P 52.982,83.82 r180 top
P15 "09-65-2028" SHDR2W165P0X396_1X2_716X1062X1425P 44.346,83.82 r180 top
Q1 "IRLML6346" SMD_SOT-23 53.213,71.755 r90 top
R1 "499" SMD_RES_0603 18.161,10.16 r0 top
R2 "0" SMD_RES_0603 24.638,18.161 r0 top
R3 "D.N.P." SMD_RES_0603 24.638,19.812 r0 top
R4 "523" SMD_RES_0603 14.986,13.081 r0 top
R5 "25" SMD_RES_0603 24.638,16.129 r0 top
R6 "499" SMD_RES_0603 14.986,17.399 r0 top
R7 "25" SMD_RES_0603 24.638,14.351 r0 top
R8 "499" SMD_RES_0603 19.304,19.812 r0 top
R9 "49.9" SMD_RES_0603 10.922,16.764 r90 top
R10 "D.N.P." SMD_RES_0603 24.638,21.463 r180 top
R11 "D.N.P." SMD_RES_0603 28.321,6.223 r180 top
R12 "0" SMD_RES_0603 28.321,3.048 r180 top
R13 "D.N.P." SMD_RES_0603 28.321,1.397 r180 top
R14 "0" SMD_RES_0603 31.369,6.223 r180 top
R15 "10k" SMD_RES_0603 98.552,21.463 r225 top
R16 "0" SMD_RES_0603 117.938,18.542 r180 top
R17 "0" SMD_RES_0603 117.95,20.066 r180 top
R18 "12k" SMD_RES_0603 112.649,11.176 r180 top
R19 "10k" SMD_RES_0603 93.853,2.54 r270 top
R20 "10k" SMD_RES_0603 95.885,10.287 r90 top
R21 "10k" SMD_RES_0603 93.853,10.287 r90 top
R22 "10k" SMD_RES_0603 95.885,2.54 r90 top
R23 "1k" SMD_RES_0603 117.602,10.414 r180 top
R24 "470" SMD_RES_0603 95.25,22.987 r90 top
R25 "5k6" SMD_RES_0603 95.504,17.78 r270 top
R26 "10k" SMD_RES_0603 93.853,17.78 r90 top
R27 "10k" SMD_RES_0603 85.09,7.874 r180 bottom
R28 "0" SMD_RES_0603 84.527,49.784 r180 top
R29 "D.N.P." SMD_RES_0603 84.527,51.689 r180 top
R30 "0" SMD_RES_0603 84.527,53.594 r180 top
R31 "10k" SMD_RES_0603 91.694,46.355 r0 top
R32 "10k" SMD_RES_0603 44.069,46.228 r180 top
R33 "10k" SMD_RES_0603 46.101,52.832 r90 top
R34 "D.N.P." SMD_RES_0603 88.011,49.784 r180 top
R35 "0" SMD_RES_0603 88.011,51.689 r180 top
R36 "D.N.P." SMD_RES_0603 87.992,53.613 r180 top
R37 "10k" SMD_RES_0603 44.069,44.577 r0 top
R38 "2k2" SMD_RES_0603 21.844,81.788 r180 bottom
R39 "2k2" SMD_RES_0603 21.844,80.137 r180 bottom
R40 "2k2" SMD_RES_0603 17.018,83.82 r180 bottom
R41 "D.N.P." SMD_RES_0603 98.011,27.686 r270 top
R42 "D.N.P." SMD_RES_0603 99.535,27.686 r270 top
R43 "D.N.P." SMD_RES_0603 101.059,27.686 r270 top
R44 "D.N.P." SMD_RES_0603 102.583,27.686 r270 top
R45 "D.N.P." SMD_RES_0603 104.107,27.686 r270 top
R46 "120" SMD_RES_0603 19.304,45.212 r180 top
R47 "120" SMD_RES_0603 19.304,63.119 r180 top
R48 "100" SMD_RES_0603 11.303,46.355 r90 bottom
R49 "169" SMD_RES_0603 16.891,46.101 r270 top
R50 "169" SMD_RES_0603 16.891,64.008 r270 top
R51 "D.N.P." SMD_RES_0603 105.631,27.686 r270 top
R52 "120" SMD_RES_0603 19.304,46.99 r180 top
R53 "120" SMD_RES_0603 19.304,64.897 r180 top
R54 "D.N.P." SMD_RES_0603 107.155,27.686 r270 top
R55 "D.N.P." SMD_RES_0603 108.679,27.686 r270 top
R56 "D.N.P." SMD_RES_0603 110.203,27.686 r270 top
R57 "10k" SMD_RES_0603 61.214,8.001 r270 bottom
R58 "10k" SMD_RES_0603 63.754,8.001 r270 bottom
R59 "10k" SMD_RES_0603 66.294,8.001 r270 bottom
R60 "10k" SMD_RES_0603 68.707,8.001 r270 bottom
R61 "D.N.P." SMD_RES_0603 111.727,27.686 r270 top
R62 "470" SMD_RES_0603 62.535,22.327 r270 top
R63 "470" SMD_RES_0603 64.186,22.327 r270 top
R64 "470" SMD_RES_0603 65.837,22.327 r270 top
R65 "470" SMD_RES_0603 67.488,22.327 r270 top
R66 "D.N.P." SMD_RES_0603 113.251,27.686 r270 top
R67 "D.N.P." SMD_RES_0603 114.775,27.686 r270 top
R68 "D.N.P." SMD_RES_0603 116.299,27.686 r270 top
R69 "120" SMD_RES_0603 19.304,42.037 r180 top
R70 "120" SMD_RES_0603 19.304,59.944 r180 top
R71 "D.N.P." SMD_RES_0603 117.823,27.686 r270 top
R72 "100" SMD_RES_0603 11.303,63.246 r270 bottom
R73 "169" SMD_RES_0603 16.764,41.148 r90 top
R74 "169" SMD_RES_0603 16.764,58.928 r90 top
R75 "D.N.P." SMD_RES_0603 119.355,27.686 r270 top
R76 "120" SMD_RES_0603 19.304,40.259 r180 top
R77 "120" SMD_RES_0603 19.304,57.912 r180 top
R78 "D.N.P." SMD_RES_0603 120.879,27.686 r270 top
R79 "D.N.P." SMD_RES_0603 122.403,27.686 r270 top
R80 "D.N.P." SMD_RES_0603 123.927,27.686 r270 top
R81 "10k" SMD_RES_0603 54.229,7.874 r180 bottom
R82 "10k" SMD_RES_0603 76.2,7.874 r180 bottom
R83 "10k" SMD_RES_0603 83.439,23.241 r90 top
R84 "10k" SMD_RES_0603 75.819,23.241 r90 top
R85 "180" SMD_RES_0603 96.393,73.152 r180 top
R86 "10k" SMD_RES_0603 88.646,76.708 r180 top
R87 "470" SMD_RES_0603 73.914,78.486 r270 top
R88 "470" SMD_RES_0603 46.355,71.755 r180 top
R89 "5k36" SMD_RES_0603 78.994,75.819 r180 top
R90 "10k" SMD_RES_0603 63.627,76.708 r180 top
R91 "1k2" SMD_RES_0603 82.042,75.819 r180 top
R92 "10k" SMD_RES_0603 67.183,76.708 r180 top
R93 "100k" SMD_RES_0603 56.007,71.628 r270 top
R94 "470" SMD_RES_0603 6.985,24.638 r0 top
R95 "4k7" SMD_RES_0603 11.938,22.733 r180 top
R96 "1k2" SMD_RES_0603 15.621,22.733 r180 top
R97 "0" SMD_RES_0603 25.019,24.384 r0 top
S1 "B3S-1000" B3S-1000 84.836,6.8 r90 top
S2 "DIP switch, SPST, 4x" "DIP switch, SPST, 4x" 65,6.9 r0 top
S3 "B3S-1000" B3S-1000 54,6.8 r90 top
S4 "B3S-1000" B3S-1000 76,6.8 r90 top
U1 "LTC2250CUH#PBF" QFN-32_5mm_x_5mm 36.195,13.081 r0 top
U2 "AD8138ARZ" SMD_SOIC-8 19.304,15.24 r90 top
U3 "FT232HL" QFP50P900X900X160-48N 106.52,17.018 r135 top
U4 "93LC56BT" SOT95P270X145-6N 94.869,6.35 r90 top
U5 "EP4CE22E22C8" EQFP144_N 65,45 r0 top
U6 "EPCQ32ASI8N" SMD_SOIC-8 31.242,53.721 r90 top
U7 "93LC86A-I/SN" SO8_M 79.629,23.241 r270 top
U8 "LP5900SDX-2.5_NOPB" SON65P220X250X80-7N 89.95,73.802 r180 top
U9 "LP38500SD-ADJ_NOPB" SON50P300X250X80-9N 80.518,79.121 r270 top
U10 "LP38500SD-ADJ_NOPB" SON50P300X250X80-9N 66.114,73.799 r180 top
U11 "LP38500SD-ADJ_NOPB" SON50P300X250X80-9N 14.097,26.035 r270 top
Y1 "12MHz" SMD_XTAL_HC-49 111.346,4.699 r0 top
Y2 "50MHz" CA32C5003HLT 84.074,42.545 r90 top

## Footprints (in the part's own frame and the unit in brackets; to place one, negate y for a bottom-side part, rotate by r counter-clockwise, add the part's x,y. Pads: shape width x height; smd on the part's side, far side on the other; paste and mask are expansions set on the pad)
61300211121 [mm] "2 pins, 1 row, straight, gold plating"
  rect 1.6x1.6 hole 1.1: 1(0,0)
  round 1.6 hole 1.1: 2(2.54,0)
  silkscreen extent -1.27,-1.27 3.81,1.27, body extent -1.27,-1.27 3.81,1.27, height 8.54
B3S-1000 [mm]
  rect 1.55x1.3 smd: 1(3.975,-2.25) 2(-3.975,-2.25) 3(3.975,2.25) 4(-3.975,2.25)
  silkscreen extent -3,-3.3 5.42,3.3, body extent -3,-3.3 3,3.3, height 4.3
CA32C5003HLT [mm]
  rect 1.4x1 smd: 1(-1.1,-0.8) 2(1.1,-0.8) 3(1.1,0.8) 4(-1.1,0.8)
  silkscreen extent -1.4,-2.05 0.2,1.25, body extent -1.7,-1.25 1.7,1.25, height 1.3
CAP_Tantalum_D [mm]
  rect 2.6x2.4 smd: +(-3.202,0.007) -(3.198,0.007)
  silkscreen extent -5.33,-2.4 5.08,2.4, body extent -3.49,-2.03 3.51,2.04, height 2.9
"DIP switch, SPST, 4x" [mm] "DIP switch, SPST, 4x"
  round 1.4 hole 0.8: 1(-3.81,-3.81) 2(-3.81,3.81) 3(-1.27,-3.81) 4(-1.27,3.81) 5(1.27,-3.81) 6(1.27,3.81) 7(3.81,-3.81) 8(3.81,3.81)
  silkscreen extent -7.03,-5.19 5.84,5.08, body extent -5.58,-4.8 5.58,4.8, height 6.3
EQFP144_N [mm] "Thin QFP, 144-Leads, Body 20x20mm, Pitch 0.5mm, IPC Medium Density"
  oval 1.8x0.3 smd: 1(-10.55,8.75) 2(-10.55,8.25) 3(-10.55,7.75) 4(-10.55,7.25) 5(-10.55,6.75) 6(-10.55,6.25) 7(-10.55,5.75) 8(-10.55,5.25) 9(-10.55,4.75) 10(-10.55,4.25) 11(-10.55,3.75) 12(-10.55,3.25) 13(-10.55,2.75) 14(-10.55,2.25) 15(-10.55,1.75) 16(-10.55,1.25) 17(-10.55,0.75) 18(-10.55,0.25) 19(-10.55,-0.25) 20(-10.55,-0.75) 21(-10.55,-1.25) 22(-10.55,-1.75) 23(-10.55,-2.25) 24(-10.55,-2.75) 25(-10.55,-3.25) 26(-10.55,-3.75) 27(-10.55,-4.25) 28(-10.55,-4.75) 29(-10.55,-5.25) 30(-10.55,-5.75) 31(-10.55,-6.25) 32(-10.55,-6.75) 33(-10.55,-7.25) 34(-10.55,-7.75) 35(-10.55,-8.25) 36(-10.55,-8.75) 73(10.55,-8.75) 74(10.55,-8.25) 75(10.55,-7.75) 76(10.55,-7.25) 77(10.55,-6.75) 78(10.55,-6.25) 79(10.55,-5.75) 80(10.55,-5.25) 81(10.55,-4.75) 82(10.55,-4.25) 83(10.55,-3.75) 84(10.55,-3.25) 85(10.55,-2.75) 86(10.55,-2.25) 87(10.55,-1.75) 88(10.55,-1.25) 89(10.55,-0.75) 90(10.55,-0.25) 91(10.55,0.25) 92(10.55,0.75) 93(10.55,1.25) 94(10.55,1.75) 95(10.55,2.25) 96(10.55,2.75) 97(10.55,3.25) 98(10.55,3.75) 99(10.55,4.25) 100(10.55,4.75) 101(10.55,5.25) 102(10.55,5.75) 103(10.55,6.25) 104(10.55,6.75) 105(10.55,7.25) 106(10.55,7.75) 107(10.55,8.25) 108(10.55,8.75)
  oval 0.3x1.8 smd: 37(-8.75,-10.55) 38(-8.25,-10.55) 39(-7.75,-10.55) 40(-7.25,-10.55) 41(-6.75,-10.55) 42(-6.25,-10.55) 43(-5.75,-10.55) 44(-5.25,-10.55) 45(-4.75,-10.55) 46(-4.25,-10.55) 47(-3.75,-10.55) 48(-3.25,-10.55) 49(-2.75,-10.55) 50(-2.25,-10.55) 51(-1.75,-10.55) 52(-1.25,-10.55) 53(-0.75,-10.55) 54(-0.25,-10.55) 55(0.25,-10.55) 56(0.75,-10.55) 57(1.25,-10.55) 58(1.75,-10.55) 59(2.25,-10.55) 60(2.75,-10.55) 61(3.25,-10.55) 62(3.75,-10.55) 63(4.25,-10.55) 64(4.75,-10.55) 65(5.25,-10.55) 66(5.75,-10.55) 67(6.25,-10.55) 68(6.75,-10.55) 69(7.25,-10.55) 70(7.75,-10.55) 71(8.25,-10.55) 72(8.75,-10.55) 109(8.75,10.55) 110(8.25,10.55) 111(7.75,10.55) 112(7.25,10.55) 113(6.75,10.55) 114(6.25,10.55) 115(5.75,10.55) 116(5.25,10.55) 117(4.75,10.55) 118(4.25,10.55) 119(3.75,10.55) 120(3.25,10.55) 121(2.75,10.55) 122(2.25,10.55) 123(1.75,10.55) 124(1.25,10.55) 125(0.75,10.55) 126(0.25,10.55) 127(-0.25,10.55) 128(-0.75,10.55) 129(-1.25,10.55) 130(-1.75,10.55) 131(-2.25,10.55) 132(-2.75,10.55) 133(-3.25,10.55) 134(-3.75,10.55) 135(-4.25,10.55) 136(-4.75,10.55) 137(-5.25,10.55) 138(-5.75,10.55) 139(-6.25,10.55) 140(-6.75,10.55) 141(-7.25,10.55) 142(-7.75,10.55) 143(-8.25,10.55) 144(-8.75,10.55)
  rect 4.3x4.3 smd: 145(0,0)
  silkscreen extent -10.67,-9.25 9.25,9.57, body extent -10,-10 10,10, height 1.6
QFN-32_5mm_x_5mm [mm] "QFN, 32-Leads, Body 5x5mm, Pitch 0.5mm, Thermal Pad 3.3x3.3mm, Silicon Labs Recommended"
  oval 0.8x0.25 smd paste+0 mask+0.06: 1(-2.425,1.75) 2(-2.425,1.25) 3(-2.425,0.75) 4(-2.425,0.25) 5(-2.425,-0.25) 6(-2.425,-0.75) 7(-2.425,-1.25) 8(-2.425,-1.75) 17(2.425,-1.75) 18(2.425,-1.25) 19(2.425,-0.75) 20(2.425,-0.25) 21(2.425,0.25) 22(2.425,0.75) 23(2.425,1.25) 24(2.425,1.75)
  oval 0.25x0.8 smd paste+0 mask+0.06: 9(-1.75,-2.425) 10(-1.25,-2.425) 11(-0.75,-2.425) 12(-0.25,-2.425) 13(0.25,-2.425) 14(0.75,-2.425) 15(1.25,-2.425) 16(1.75,-2.425) 25(1.75,2.425) 26(1.25,2.425) 27(0.75,2.425) 28(0.25,2.425) 29(-0.25,2.425) 30(-0.75,2.425) 31(-1.25,2.425) 32(-1.75,2.425)
  rect 3.2x3.2 smd paste-1.65 mask+0.06: 33(0,0)
  silkscreen extent -3.47,-2.7 2.7,2.7, body extent -2.55,-2.55 2.55,2.55, height 1
QFP50P900X900X160-48N [mm]
  rect 1.475x0.3 smd: 1(-4.238,2.75) 2(-4.238,2.25) 3(-4.238,1.75) 4(-4.238,1.25) 5(-4.238,0.75) 6(-4.238,0.25) 7(-4.238,-0.25) 8(-4.238,-0.75) 9(-4.238,-1.25) 10(-4.238,-1.75) 11(-4.238,-2.25) 12(-4.238,-2.75) 25(4.238,-2.75) 26(4.238,-2.25) 27(4.238,-1.75) 28(4.238,-1.25) 29(4.238,-0.75) 30(4.238,-0.25) 31(4.238,0.25) 32(4.238,0.75) 33(4.238,1.25) 34(4.238,1.75) 35(4.238,2.25) 36(4.238,2.75)
  rect 0.3x1.475 smd: 13(-2.75,-4.238) 14(-2.25,-4.238) 15(-1.75,-4.238) 16(-1.25,-4.238) 17(-0.75,-4.238) 18(-0.25,-4.238) 19(0.25,-4.238) 20(0.75,-4.238) 21(1.25,-4.238) 22(1.75,-4.238) 23(2.25,-4.238) 24(2.75,-4.238) 37(2.75,4.238) 38(2.25,4.238) 39(1.75,4.238) 40(1.25,4.238) 41(0.75,4.238) 42(0.25,4.238) 43(-0.25,4.238) 44(-0.75,4.238) 45(-1.25,4.238) 46(-1.75,4.238) 47(-2.25,4.238) 48(-2.75,4.238)
  silkscreen extent -4.85,-3.15 3.15,3.62, body extent -4.5,-4.5 4.5,4.5, height 1.6
SHDR2W165P0X396_1X2_716X1062X1425P [mm]
  rect 3x3 hole 1.8: 1(0,0)
  round 3 hole 1.8: 2(3.96,0)
  silkscreen extent -1.75,-5.65 5.71,5.6, body extent -1.58,-5.6 5.58,5.15, height 13.85
sm_esd_0603 [mm]
  rect 1.02x0.76 smd: 1(-0.76,0) 2(0.76,0)
  body extent -0.83,-0.4 0.83,0.4, height 0.35
SMA5.08-H [mm] "Connector; RF Coaxial, MCX, Thru-Hole; 5 Position; Right Angle"
  round 2.4 hole 1.5: 1(0,0)
  round 2.8 hole 1.7: 2(-2.54,-2.54) 3(2.54,-2.54) 4(2.54,2.54) 5(-2.54,2.54)
  silkscreen extent -3,-3 3,3, body extent -6.5,-3 3,3, height 5.99
SMD_CAPACITOR_0402 [mm]
  rect 0.5x0.6 smd: 1(-0.5,0) 2(0.5,0)
  body extent -0.5,-0.3 0.5,0.3, height 0.2
SMD_CAPACITOR_0603 [mm]
  rect 0.87x1.02 smd: 1(-0.68,0) 2(0.68,0)
  body extent -0.8,-0.4 0.8,0.4, height 1
SMD_CAPACITOR_1206 [mm]
  rect 1.52x1.6 smd: 1(-1.71,0) 2(1.71,0)
  silkscreen extent -0.7,-0.8 0.7,0.8, body extent -1.6,-0.8 1.6,0.8, height 1.58
SMD_CAPACITOR_POL_A_3216 [mm]
  rect 1.8x1.25 smd: 1(-1.3,0) 2(1.3,0)
  silkscreen extent -2.15,-0.89 1.5,0.89, body extent -1.6,-0.8 1.6,0.8, height 1.8
SMD_DO-214AC [mm]
  rect 2.65x1.75 smd: 1(-2.15,0) 2(2.15,0)
  silkscreen extent -2.2,-1.4 2.2,1.4, body extent -2.5,-1.35 2.5,1.35, height 2.19
SMD_INDUCTOR_7.3MM [mm]
  rect 2.1x2.8 smd: 1(-3.45,0) 2(3.45,0)
  silkscreen extent -3.65,-3.65 3.65,3.65, body extent -3.65,-3.65 3.65,3.65, height 4
SMD_LED_0603 [mm]
  rect 1.2x0.7 smd: 1(0.75,0) 2(-0.75,0)
  silkscreen extent -1.2,-0.51 0.8,0.51, body extent -0.8,-0.4 0.8,0.4, height 0.36
SMD_RES_0603 [mm]
  rect 0.9x1 smd: 1(-0.75,0) 2(0.75,0)
  body extent -0.75,-0.4 0.8,0.4, height 0.55
SMD_RESISTOR_1206 [mm]
  rect 1.52x1.6 smd: 1(-1.71,0) 2(1.71,0)
  silkscreen extent -0.7,-0.8 0.7,0.8, body extent -1.6,-0.81 1.6,0.81, height 0.61
SMD_SOD-323 [mm]
  rect 1.088x0.55 smd: 1(1.158,0) 2(-1.158,0)
  silkscreen extent -1.7,-0.64 0.82,0.64, body extent -1.3,-0.64 1.3,0.64, height 1.17
SMD_SOIC-8 [mm]
  rect 1.78x0.72 smd: 1(-2.34,1.905) 2(-2.34,0.635) 3(-2.34,-0.635) 4(-2.34,-1.905) 5(2.34,-1.905) 6(2.34,-0.635) 7(2.34,0.635) 8(2.34,1.905)
  silkscreen extent -2,-2.5 2,2.5, body extent -2,-2.5 2,2.5, height 1.44
SMD_SOT-23 [mm]
  rect 0.65x1.1 smd: 1(-0.95,-1.1) 2(0.95,-1.1) 3(0,1.1)
  silkscreen extent -1.5,-0.65 1.5,0.65, body extent -1.5,-1.13 1.5,1.13, height 1.22
SMD_USB_MICRO_B [mm]
  rect 0.4x1.8 smd mask+0.05: 1(-1.3,0) 2(-0.65,0) 3(0,0) 4(0.65,0) 5(1.3,0)
  rect 2.5x1.9 smd: 5(-3.75,-2.85) 5(3.75,-2.85)
  silkscreen extent -3.8,-5 3.8,0, body extent -3.96,-5.66 3.96,0, height 2.76
SMD_XTAL_HC-49 [mm]
  rect 5.5x2 smd: 1(-4.75,0)
  rect 5.5x2 smd mask+0.1: 2(4.75,0)
  silkscreen extent -5.8,-2.4 5.8,2.4, body extent -6.4,-2.41 6.4,2.42, height 4.3
SO8_M [mm] "SOIC, 8-Leads, Body 4.9x3.9mm, Pitch 1.27mm, IPC Low Density"
  oval 2.5x0.7 smd: 1(-2.45,1.905) 2(-2.45,0.635) 3(-2.45,-0.635) 4(-2.45,-1.905) 5(2.45,-1.905) 6(2.45,-0.635) 7(2.45,0.635) 8(2.45,1.905)
  silkscreen extent -2.57,-2.5 0.8,2.93, body extent -2,-2.5 2,2.5, height 1.75
SON50P300X250X80-9N [mm]
  rect 0.85x0.3 smd: 1(-1.45,0.75) 2(-1.45,0.25) 3(-1.45,-0.25) 4(-1.45,-0.75) 5(1.45,-0.75) 6(1.45,-0.25) 7(1.45,0.25) 8(1.45,0.75)
  rect 1.7x1.6 smd: 9(0,0)
  silkscreen extent -2,1.28 -1.75,1.53, body extent -1.55,-1.25 1.55,1.25, height 0.8
SON65P220X250X80-7N [mm]
  rect 0.85x0.3 smd: 1(-1.05,0.65) 2(-1.05,0) 3(-1.05,-0.65) 4(1.05,-0.65) 5(1.05,0) 6(1.05,0.65)
  rect 0.85x1.3 smd: 7(0,0)
  silkscreen extent -1.6,1.18 -1.35,1.42, body extent -1.15,-1.25 1.15,1.25, height 0.8
SOT95P270X145-6N [mm]
  rect 1.4x0.6 smd: 1(-1.25,0.95) 2(-1.25,0) 3(-1.25,-0.95) 4(1.25,-0.95) 5(1.25,0) 6(1.25,0.95)
  silkscreen extent -1.95,-1.45 0.2,1.6, body extent -1.35,-1.45 1.35,1.45, height 1.45
THT_HEADER_2x13 [mm]
  rect 1.65x1.65 hole 1.1: 1(0,0)
  round 1.65 hole 1.1: 2(0,2.54) 3(2.54,0) 4(2.54,2.54) 5(5.08,0) 6(5.08,2.54) 7(7.62,0) 8(7.62,2.54) 9(10.16,0) 10(10.16,2.54) 11(12.7,0) 12(12.7,2.54) 13(15.24,0) 14(15.24,2.54) 15(17.78,0) 16(17.78,2.54) 17(20.32,0) 18(20.32,2.54) 19(22.86,0) 20(22.86,2.54) 21(25.4,0) 22(25.4,2.54) 23(27.94,0) 24(27.94,2.54) 25(30.48,0) 26(30.48,2.54)
  silkscreen extent -5.1,-3.16 35.78,5.94, body extent -5.1,-3.28 35.58,5.82, height 9.1
THT_HEADER_100MIL_2X3_MALE_SHROUDED [mm]
  round 1.4 hole 0.9: 1(-1.27,2.54) 2(1.27,2.54) 3(-1.27,0) 4(1.27,0) 5(-1.27,-2.54) 6(1.27,-2.54)
  silkscreen extent -4.25,-7.65 4.3,7.65, body extent -4.6,-7.61 4.25,7.61, height 9.33
THT_HEADER_100MIL_2X4_MALE_SHROUDED [mm]
  round 1.4 hole 0.9: 1(-1.27,5.08) 2(1.27,5.08) 3(-1.27,2.54) 4(1.27,2.54) 5(-1.27,0) 6(1.27,0) 7(-1.27,-2.54) 8(1.27,-2.54)
  silkscreen extent -4.25,-7.65 4.3,10.2, body extent -4.6,-7.61 4.25,10.15, height 9.33
THT_HEADER_100MIL_2X5_MALE_SHROUDED [mm]
  round 1.4 hole 0.9: 1(-1.27,5.08) 2(1.27,5.08) 3(-1.27,2.54) 4(1.27,2.54) 5(-1.27,0) 6(1.27,0) 7(-1.27,-2.54) 8(1.27,-2.54) 9(-1.27,-5.08) 10(1.27,-5.08)
  silkscreen extent -4.25,-10.2 4.3,10.2, body extent -4.6,-10.15 4.25,10.15, height 9.33
THT_POWER_JACK_2.1/2.5 [mil]
  oval 80x178 hole 40 slot 138 at 90 deg: 1(-236.22,0)
  oval 166x80 hole 40 slot 126 at 0 deg: 2(-120.08,188.98)
  oval 80x166 hole 40 slot 126 at 90 deg: 3(0,0)
  silkscreen extent -264,-177 39,177, body extent -262,-177 289,193, height 433

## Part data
C1 C2 C3 C4 C5 C6 C7 C8 C9 C10 C11 C12 C13 C14 C15 C16 C17 C18 C19 C20 C21 C22 C24 C26 C27 C29 C31 C32 C33 C34 C35 C36 C37 C38 C39 C40 C41 C42 C43 C44 C45 C46 C47 C48 C49 C50 C51 C52 C53 C55 C56 C57 C58 C59 C60 C61 C62 C63 C64 C65 C66 C67 C68 C69 C70 C71 C72 C73 C74 C75 C76 C77 C78 C79 C80 C81 C82 C83 C84 C85 C86 C87 C88 C89 C90 C91 C92 C93 C94 C95 C96 C97 C98 C99 C100 C101 C102 C103 C104 C105 C106 C107 C108 C109 C110 C112 C113 C114 C115 C116 C117 C118 C119 C120 C121 C125 C126 C127 C128 C129 C130 C131 C132 C133 C134 C135 C136 C137 C138 C139 C140 C141 C142 C143 C144: library part Capacitor
C23 C25 C28 C30 C54 C111 C122 C123 C124: library part Capacitor_pol
D1 D2 D3: library part ESD_suppressor_bidir_5V, "ESD suppressor, 5V", Manufacturer=Bourns, Package=0603, Part Number=652-CG0603MLC-05LEA
D4 D5 D6 D7 D8 D9 D13 D15 D16 D17: library part LED
D10 D11 D14: library part Schottky_Diode
D12: library part TVS_Diode_unidirect
F1 F2 F3: library part Fuse
J1: Manufacturer="Wurth Electronics", Package="2-pin, 2.54 mm", Part Number=61300211121
L1 L2 L3 L4 L5 L6 L7: library part EMI_Ferrite_bead
L8: library part Inductor
P1: library part USB_Micro_B, "Micro USB Type B"
P2 P5 P7: library part Header_2x5
P3: library part Header_2x4
P4 P8 P9: library part Header_2x3
P6: library part Header_2x8_1, "Header 2x8"
P11 P12 P14 P15: "Connector", Manufacturer_Name=Molex, Mouser Part Number=538-09-65-2028, RS Part Number=6705237P
P13: library part Power_JACK_2.1/2.5, "Low Voltage Power Supply Connector"
Q1: library part Transistor_N-Mosfet
R1 R2 R3 R4 R5 R6 R7 R8 R9 R10 R11 R12 R13 R14 R15 R16 R17 R18 R19 R20 R21 R22 R23 R24 R25 R26 R27 R28 R29 R30 R31 R32 R33 R34 R35 R36 R37 R38 R39 R40 R41 R42 R43 R44 R45 R46 R47 R48 R49 R50 R51 R52 R53 R54 R55 R56 R57 R58 R59 R60 R61 R62 R63 R64 R65 R66 R67 R68 R69 R70 R71 R72 R73 R74 R75 R76 R77 R78 R79 R80 R81 R82 R83 R84 R85 R86 R87 R88 R89 R90 R91 R92 R93 R94 R95 R96 R97: library part Resistor
S1 S3 S4: "SWITCH TACTILE SPST-NO 0.05A 24V", Manufacturer=OMRON, Package="6 mm x 6 mm"
S2: Manufacturer="Wurth Electronics", Package=DIP, Part Number=418117270904
U1: "Analog to digital converter_10bit_105MS/s"
U2: "Low Distortion,Differential ADC Driver"
U3: library part FT232HL-REEL, "Single Channel Hi-Speed USB to Multipurpose UART/FIFO"
U4: library part 93LC56BT-E_OT, "EEPROM"
U5: "Cyclone IV Family FPGA, 2V Core, 79 I/O Pins, 4 PLLs, 144-Pin QFP, Speed Grade 8, Commercial Grade", Supplier Part Number 1=EP4CE22E22C8-ND
U6: library part EPCS16SI8N, "Serial Configuration Memory"
U7: Manufacturer=Microchip, Package=SOIC-8
U8 U9 U10 U11: "LDO"
Y1: library part XTAL_2pin
Y2: library part CA32C5003HLT, "Crystal or Oscillator"

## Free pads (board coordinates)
  round 8 hole 3.2: 2(5,5) 2(5,85) 2(125,5) 2(125,85)

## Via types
v1: diameter 0.5, hole 0.2, Component Side to Bottom Layer, 759 vias
v2: diameter 0.66, hole 0.33, Component Side to Bottom Layer, tented top, 16 vias

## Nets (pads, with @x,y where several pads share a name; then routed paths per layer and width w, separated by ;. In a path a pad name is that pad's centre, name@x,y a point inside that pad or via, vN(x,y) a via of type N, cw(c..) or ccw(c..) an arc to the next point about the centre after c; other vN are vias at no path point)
+1V2: C81.2 C82.2 C83.2 C84.2 C85.2 C86.2 C87.2 C88.2 C89.2 C90.2 C91.2 C92.2 C93.2 C94.2 C95.2 C96.2 C97.2 C98.2 C99.2 C100.2 C101.2 C102.2 C103.2 C104.2 C105.2 C106.2 C107.2 C108.2 C109.2 C110.2 C111.+ C135.2 C136.2 L6.1 Q1.1 R90.2 R93.2 U5.5 U5.29 U5.34 U5.38 U5.45 U5.61 U5.70 U5.78 U5.84 U5.102 U5.116 U5.124 U5.134 U5.138 U10.5 U10.6 U10.7 | length 86.6
  Component Side w0.254: Q1.1@54.313,70.805 57.343,70.805 58.293,71.755 v1(58.293,75.057) ; U5.34@54.45,37.25 55.538,37.25 v1(55.927,37.639) ; U5.29@54.45,39.75 v1(55.879,39.75) ; U5.5@54.45,51.75 v1(55.913,51.75) ; v1(56.308,36.115) 56.75,35.673 U5.38@56.75,34.45 ; U5.138@59.25,55.55 59.25,54.415 v1(59.69,53.975) ; U5.45@60.25,34.45 v1(60.25,35.983) ; C136.2@61.087,74.989 61.158,74.989 R90.2@62.877,76.708 ; v1(61.25,54.033) U5.134@61.25,55.55 ; C135.2@62.992,73.959 C135.2@63.067,73.959 ; C135.2@63.082,74.049 C135.2@63.157,74.049 ; U10.7@64.664,73.549 63.477,73.549 C135.2@63.067,73.959 ; U10.6@64.664,74.049 C135.2@63.157,74.049 ; U10.5@64.664,74.549 63.657,74.549 C135.2@63.157,74.049 ; v1(66.25,54.058) U5.124@66.25,55.55 ; v1(67.818,35.941) 67.818,35.916 68.254,35.48 68.25,35.476 U5.61@68.25,34.45 ; U5.116@70.25,55.55 70.25,54.431 70.405,54.276 v1(70.405,54.022) ; v1(72.683,35.996) 72.683,35.615 72.75,35.548 U5.70@72.75,34.45 ; v1(73.834,38.782) 74.215,38.782 74.247,38.75 U5.78@75.55,38.75 ; v1(73.834,41.83) 74.342,41.83 74.422,41.75 U5.84@75.55,41.75 ; v1(74.058,50.75) U5.102@75.55,50.75 ; C135.2@63.067,73.959 C135.2@63.157,74.049
  Component Side w0.508: C135.2@62.992,73.959 C135.2@63.082,74.049
  Component Side w1.016: v1(58.293,75.057) v1(58.928,75.057) v1(59.563,75.057) 61.019,75.057 C136.2@61.087,74.989 62.117,73.959 C135.2@62.992,73.959
  Bottom Layer w0.254: L6.1@51.482,58.582 L6.1@51.609,58.709 ; v1(55.879,39.75) 56.76,39.75 C105.2@56.816,39.806 C106.2@57.959,39.806 v1(58.84,39.806) ; v1(55.913,51.75) 55.919,51.744 C107.2@56.816,51.744 C108.2@57.959,51.744 v1(57.959,50.974) ; v1(55.927,37.639) 56.681,37.639 C103.2@56.816,37.774 C104.2@57.959,37.774 v1(58.84,37.774) ; v1(56.308,36.115) 56.054,35.861 C101.2@56.054,34.964 C102.2@57.07,34.964 v1(57.07,36.877) ; v1(59.237,51.109) C82.2@59.237,51.99 C81.2@59.237,53.133 59.237,53.522 v1(59.69,53.975) ; v1(60.25,35.983) 60.25,36.874 C99.2@60.253,36.877 C100.2@60.253,38.02 v1(60.253,39.028) ; v1(61.25,54.033) 61.25,53.66 C83.2@61.777,53.133 C84.2@61.777,51.99 v1(61.777,51.109) ; v1(65.96,51.99) C86.2@66.73,51.99 C85.2@66.73,53.133 ; v1(66.25,54.058) 66.25,53.74 C85.2@66.73,53.26 ; v1(67.818,35.941) 67.818,36.441 C97.2@68.254,36.877 C98.2@68.254,38.02 v1(68.254,38.901) ; C87.2@70.25,53.28 70.27,53.26 70.27,53.887 v1(70.405,54.022) ; C87.2@70.27,53.133 C88.2@70.27,51.99 v1(71.04,51.99) ; v1(70.913,42.719) 70.921,42.711 C92.2@71.802,42.711 C91.2@72.945,42.711 72.953,42.711 v1(73.834,41.83) ; v1(70.921,39.171) C93.2@71.802,39.171 C94.2@72.945,39.171 73.334,38.782 v1(73.834,38.782) ; v1(71.04,50.847) 71.921,50.847 C90.2@71.929,50.855 C89.2@73.072,50.855 73.732,50.855 73.837,50.75 v1(74.058,50.75) ; v1(72.683,35.996) C95.2@72.683,36.877 C96.2@72.683,38.02 v1(73.453,38.02)
  other v1: 62.912,38.655 63.801,38.655 62.023,39.417 62.023,40.052 62.023,40.687 62.912,41.449 63.801,41.449 60.372,47.926 61.261,47.926 59.483,48.688 59.483,49.323 59.483,49.958 60.372,50.72 61.261,50.72 53.26,58.975 58.209,58.975 53.972,59.356 57.574,59.356 51.482,59.737 53.26,59.737 58.209,59.737 53.972,60.118 57.574,60.118 51.482,60.499 53.26,60.499 58.209,60.499 53.972,60.88 57.574,60.88 53.26,61.261 58.209,61.261 53.972,61.642 57.574,61.642 54.657,61.896 53.26,62.023
+2V5: C127.2 C128.2 L7.2 P5.4 R38.2 R39.2 R85.2 U8.1 | length 89.6
  Component Side w0.254: C128.2@94.107,73.025 94.133,73.098 94.152,73.152 R85.2@95.643,73.152
  Component Side w0.508: U8.1@91,73.152 C127.2@92.538,73.152 ; C127.2@92.583,73.107 C128.2@94.107,73.107 ; C128.2@94.103,73.025 C128.2@94.107,73.025
  Component Side w1.016: v1(94.107,70.993) v1(94.107,71.628) v1(94.107,72.263) 94.107,73.025 C128.2@94.107,73.107
  Bottom Layer w0.254: R38.2@21.082,82.181 21.082,85.09 P5.4@22.352,86.36 ; R39.2@21.094,80.137 R38.2@21.094,81.788
  Bottom Layer w1.016: P5.4@22.352,86.36 24.257,88.265 35.052,88.265 37.084,86.233 37.084,81.534 39.624,78.994 76.327,78.994 83.693,71.628 v1(85.344,71.628) v1(86.106,71.628) ; L7.2@80.887,59.944 v1(81.915,59.944) v1(82.55,59.944) v1(83.185,59.944)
